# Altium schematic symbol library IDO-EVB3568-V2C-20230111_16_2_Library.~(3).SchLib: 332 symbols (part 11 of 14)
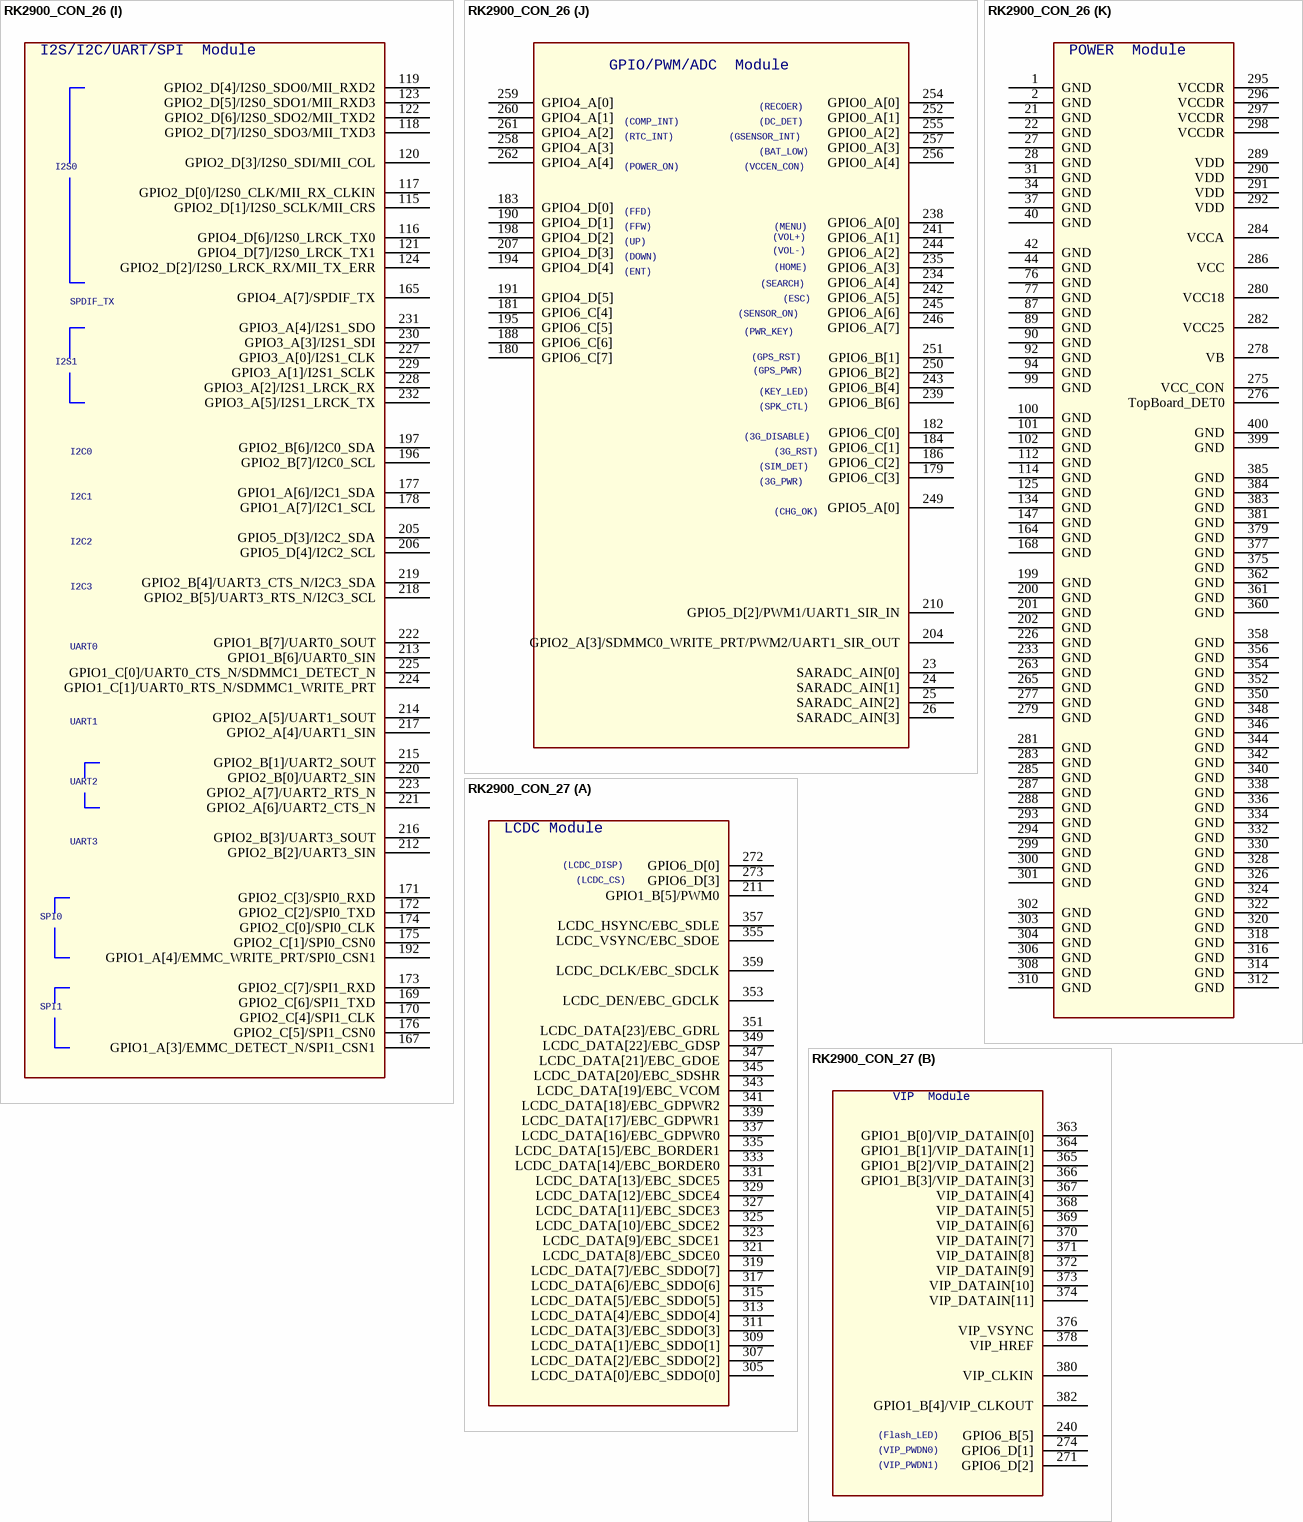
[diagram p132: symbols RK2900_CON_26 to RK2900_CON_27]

## RK2900_CON_26
designator U?
Altium-Right: 120; Altium-Bottom: 650; Altium-Right1: 160; Altium-Bottom1: 390; Altium-Right2: 140; Altium-Bottom2: 270; Altium-Right3: 280; Altium-Bottom3: 520; Altium-Right4: 170; Altium-Bottom4: 240; Altium-Right5: 190; Altium-Bottom5: 530; Altium-Right6: 290; Altium-Bottom6: 300; Altium-Right7: 220; Altium-Bottom7: 340; Altium-Right8: 180; Altium-Bottom8: 200; Altium-Bottom9: 690; Altium-Right10: 250; Altium-Bottom10: 470
footprint RK2900_TOP
part A pins: 211 GPIO1_B[5]/PWM0, 272 GPIO6_D[0], 273 GPIO6_D[3], 305 LCDC_DATA[0]/EBC_SDDO[0], 307 LCDC_DATA[2]/EBC_SDDO[2], 309 LCDC_DATA[1]/EBC_SDDO[1], 311 LCDC_DATA[3]/EBC_SDDO[3], 313 LCDC_DATA[4]/EBC_SDDO[4], 315 LCDC_DATA[5]/EBC_SDDO[5], 317 LCDC_DATA[6]/EBC_SDDO[6], 319 LCDC_DATA[7]/EBC_SDDO[7], 321 LCDC_DATA[8]/EBC_SDCE0, 323 LCDC_DATA[9]/EBC_SDCE1, 325 LCDC_DATA[10]/EBC_SDCE2, 327 LCDC_DATA[11]/EBC_SDCE3, 329 LCDC_DATA[12]/EBC_SDCE4, 331 LCDC_DATA[13]/EBC_SDCE5, 333 LCDC_DATA[14]/EBC_BORDER0, 335 LCDC_DATA[15]/EBC_BORDER1, 337 LCDC_DATA[16]/EBC_GDPWR0, 339 LCDC_DATA[17]/EBC_GDPWR1, 341 LCDC_DATA[18]/EBC_GDPWR2, 343 LCDC_DATA[19]/EBC_VCOM, 345 LCDC_DATA[20]/EBC_SDSHR, 347 LCDC_DATA[21]/EBC_GDOE, 349 LCDC_DATA[22]/EBC_GDSP, 351 LCDC_DATA[23]/EBC_GDRL, 353 LCDC_DEN/EBC_GDCLK, 355 LCDC_VSYNC/EBC_SDOE, 357 LCDC_HSYNC/EBC_SDLE, 359 LCDC_DCLK/EBC_SDCLK
part B pins: 240 GPIO6_B[5], 271 GPIO6_D[2], 274 GPIO6_D[1], 363 GPIO1_B[0]/VIP_DATAIN[0], 364 GPIO1_B[1]/VIP_DATAIN[1], 365 GPIO1_B[2]/VIP_DATAIN[2], 366 GPIO1_B[3]/VIP_DATAIN[3], 367 VIP_DATAIN[4], 368 VIP_DATAIN[5], 369 VIP_DATAIN[6], 370 VIP_DATAIN[7], 371 VIP_DATAIN[8], 372 VIP_DATAIN[9], 373 VIP_DATAIN[10], 374 VIP_DATAIN[11], 376 VIP_VSYNC, 378 VIP_HREF, 380 VIP_CLKIN, 382 GPIO1_B[4]/VIP_CLKOUT
part C pins: 3 GPIO0_C[6]/EBC_SDCE4/SMC_DATA[14], 4 GPIO0_C[7]/EBC_SDCE5/SMC_DATA[15], 5 GPIO0_C[0]/EBC_GDSP/SMC_DATA[8], 6 GPIO0_C[1]/EBC_GDRL/SMC_DATA[9], 7 GPIO0_B[3]/EBC_BORDER0/SMC_ADDR[3]/HOST_DATA[3], 8 GPIO0_B[4]/EBC_BORDER1/SMC_WEN, 9 GPIO0_D[1]/EBC_GDCLK/SMC_ADDR[4]/HOST_DATA[4], 10 GPIO0_B[2]/EBC_SDCE2/SMC_ADDR[2]/HOST_DATA[2], 11 GPIO0_C[3]/EBC_GDPWR1/SMC_DATA[11], 12 GPIO0_B[7]/EBC_GDOE/SMC_OEN, 13 GPIO0_D[0]/EBC_SDOE/SMC_ADVN, 14 GPIO5_C[6]/EBC_SDDO[6]/SMC_DATA[6], 15 GPIO0_C[5]/EBC_SDCE3/SMC_DATA[13], 16 GPIO0_B[1]/EBC_SDCE1/SMC_ADDR[1]/HOST_DATA[1], 17 GPIO5_C[5]/EBC_SDDO[5]/SMC_DATA[5], 18 GPIO3_D[5]/SMC_ADDR[7]/HOST_DATA[7], 19 GPIO1_A[2]/SMC_CSN1, 20 GPIO0_C[4]/EBC_GDPWR2/SMC_DATA[12], 43 GPIO3_D[6]/SMC_ADDR[8]/HOST_DATA[8], 150 GPIO3_D[4]/HOST_WRN, 151 GPIO3_D[3]/HOST_RDN, 152 GPIO3_D[2]/HOST_CSN, 153 GPIO3_D[7]/SMC_ADDR[9]/HOST_DATA[9], 154 GPIO3_A[6]/SMC_ADDR[14]/HOST_DATA[14], 155 GPIO3_C[7]/SMC_ADDR[17]/HOST_DATA[17], 156 GPIO3_C[3]/SMC_ADDR[10]/HOST_DATA[10], 157 GPIO3_C[4]/SMC_ADDR[11]/HOST_DATA[11], 158 GPIO3_D[1]/SMC_ADDR[19]/HOST_ADDR1, 159 GPIO3_C[5]/SMC_ADDR[12]/HOST_DATA[12], 160 GPIO3_C[2]/SMC_ADDR[13]/HOST_DATA[13], 161 GPIO3_C[6]/SMC_ADDR[16]/HOST_DATA[16], 162 GPIO3_A[7]/SMC_ADDR[15]/HOST_DATA[15], 163 GPIO3_D[0]/SMC_ADDR[18]/HOST_ADDR0, 386 GPIO1_A[1]/SMC_CSN0, 387 GPIO5_C[4]/EBC_SDDO[4]/SMC_DATA[4], 388 GPIO5_D[1]/EBC_SDCLK/SMC_ADDR[6]/HOST_DATA[6], 389 GPIO0_B[5]/EBC_VCOM/SMC_BLSN0, 390 GPIO5_C[0]/EBC_SDDO[0]/SMC_DATA[0], 391 GPIO5_D[0]/EBC_SDLE/SMC_ADDR[5]/HOST_DATA[5], 392 GPIO5_C[1]/EBC_SDDO[1]/SMC_DATA[1], 393 GPIO0_B[6]/EBC_SDSHR/SMC_BLSN1/HOST_INT, 394 GPIO0_C[2]/EBC_GDPWR0/SMC_DATA[10], 395 GPIO5_C[2]/EBC_SDDO[2]/SMC_DATA[2], 396 GPIO5_C[3]/EBC_SDDO[3]/SMC_DATA[3], 397 GPIO5_C[7]/EBC_SDDO[7]/SMC_DATA[7], 398 GPIO0_B[0]/EBC_SDCE0/SMC_ADDR[0]/HOST_DATA[0]
part D pins: 29 OTG_DP, 30 OTG_DM, 32 HOST20_DM, 33 HOST20_DP, 35 HOST11_DM, 36 HOST11_DP, 38 OTG_ID, 39 OTG_VBUS, 41 RTCINT_OUT, 166 GPIO4_A[5]/OTG_DRV_VBUS, 187 GPIO4_A[6]/HOST20_DRV_VBUS, 264 NPOR
part E pins: 45 FLASH_ALE, 46 FLASH_DATA[1], 47 FLASH_RDY, 48 FLASH_RDN, 49 GPIO4_B[4]/FLASH_DATA[12], 50 FLASH_DATA[0], 51 FLASH_DATA[4], 52 GPIO4_B[7]/FLASH_DATA[15], 53 GPIO4_B[5]/FLASH_DATA[13], 54 FLASH_CLE, 55 GPIO4_B[1]/FLASH_DATA[9], 56 FLASH_DATA[5], 57 FLASH_CSN0, 58 FLASH_DATA[6], 59 GPIO4_B[0]/FLASH_DATA[8], 60 FLASH_DATA[7], 61 FLASH_DATA[2], 62 FLASH_DATA[3], 63 GPIO0_D[7]/FLASH_CSN6, 64 FLASH_WP, 65 FLASH_WRN, 66 GPIO4_B[6]/FLASH_DATA[14], 67 GPIO0_D[3]/FLASH_CSN2, 68 GPIO0_D[4]/FLASH_CSN3, 69 GPIO0_D[2]/FLASH_CSN1, 70 GPIO0_D[6]/FLASH_CSN5, 71 GPIO1_A[0]/FLASH_CSN7/MDDR_TQ, 72 GPIO0_A[5]/FLASH_DQS, 73 GPIO0_D[5]/FLASH_CSN4, 74 GPIO4_B[2]/FLASH_DATA[10], 75 GPIO4_B[3]/FLASH_DATA[11], 78 GPIO3_B[3]/EMMC_DATA1, 79 GPIO3_B[1]/EMMC_CMD, 80 GPIO3_B[6]/EMMC_DATA4, 81 GPIO3_C[1]/EMMC_DATA7, 82 GPIO3_B[5]/EMMC_DATA3, 83 GPIO3_B[4]/EMMC_DATA2, 84 GPIO3_B[2]/EMMC_DATA0, 85 GPIO3_C[0]/EMMC_DATA6, 86 GPIO3_B[7]/EMMC_DATA5, 88 GPIO3_B[0]/EMMC_CLKOUT, 203 GPIO1_A[5]/EMMC_PWR_EN/PWM3, 237 GPIO6_B[7]
part F pins: 91 GPIO1_C[2]/SDMMC1_CMD, 93 GPIO1_C[7]/SDMMC1_CLKOUT, 95 GPIO1_C[4]/SDMMC1_DATA1, 96 GPIO1_C[3]/SDMMC1_DATA0, 97 GPIO1_C[6]/SDMMC1_DATA3, 98 GPIO1_C[5]/SDMMC1_DATA2, 103 GPIO1_D[3]/SDMMC0_DATA1, 104 GPIO1_D[1]/SDMMC0_CMD, 105 GPIO1_D[5]/SDMMC0_DATA3, 106 GPIO2_A[1]/SDMMC0_DATA7, 107 GPIO1_D[7]/SDMMC0_DATA5, 108 GPIO1_D[2]/SDMMC0_DATA0, 109 GPIO2_A[0]/SDMMC0_DATA6, 110 GPIO1_D[6]/SDMMC0_DATA4, 111 GPIO1_D[4]/SDMMC0_DATA2, 113 GPIO1_D[0]/SDMMC0_CLKOUT, 185 GPIO5_D[7], 193 GPIO2_A[2]/SDMMC0_DETECT_N, 208 GPIO5_D[5]/SDMMC0_PWR_EN, 209 GPIO5_D[6]/SDMMC1_PWR_EN
part G pins: 126 GPIO4_C[7]/RMII_RXD0/MII_RXD0, 127 GPIO4_C[3]/RMII_TXD0/MII_TXD0, 128 GPIO4_C[6]/RMII_RXD1/MII_RXD1, 129 GPIO4_C[1]/RMII_TX_EN/MII_TX_EN, 130 GPIO4_C[0]/RMII_CLKOUT/RMII_CLKIN, 131 GPIO4_C[2]/RMII_TXD1/MII_TXD1, 132 GPIO4_C[5]/RMII_CRS_DVALID/MII_RXD_VALID, 133 GPIO4_C[4]/RMII_RX_ERR/MII_RX_ERR, 148 GPIO5_A[3]/MII_TX_CLKIN, 149 GPIO0_A[6]/MII_MD, 189 GPIO0_A[7]/MII_MDCLK, 236 GPIO5_A[2], 248 GPIO6_B[0], 253 GPIO5_A[1], 266 TRST_N, 267 TCK, 268 TDI, 269 TMS, 270 TDO
part H pins: 135 GPIO5_A[7]/HSADC_DATA2, 136 GPIO5_B[5]/HSADC_DATA8/TS_VALID, 137 GPIO5_A[5]/HSADC_DATA0, 138 GPIO5_B[1]/HSADC_DATA4, 139 GPIO5_B[0]/HSADC_DATA3, 140 GPIO5_A[6]/HSADC_DATA1, 141 GPIO5_B[3]/HSADC_DATA6, 142 GPIO5_B[2]/HSADC_DATA5, 143 GPIO5_B[4]/HSADC_DATA7, 144 GPIO5_A[4]/TS_SYNC, 145 GPIO5_B[6]/HSADC_DATA9/TS_FAIL, 146 GPIO5_B[7]/HSADC_CLKOUT/GPS_CLK, 247 GPIO6_B[3]
part I pins: 115 GPIO2_D[1]/I2S0_SCLK/MII_CRS, 116 GPIO4_D[6]/I2S0_LRCK_TX0, 117 GPIO2_D[0]/I2S0_CLK/MII_RX_CLKIN, 118 GPIO2_D[7]/I2S0_SDO3/MII_TXD3, 119 GPIO2_D[4]/I2S0_SDO0/MII_RXD2, 120 GPIO2_D[3]/I2S0_SDI/MII_COL, 121 GPIO4_D[7]/I2S0_LRCK_TX1, 122 GPIO2_D[6]/I2S0_SDO2/MII_TXD2, 123 GPIO2_D[5]/I2S0_SDO1/MII_RXD3, 124 GPIO2_D[2]/I2S0_LRCK_RX/MII_TX_ERR, 165 GPIO4_A[7]/SPDIF_TX, 167 GPIO1_A[3]/EMMC_DETECT_N/SPI1_CSN1, 169 GPIO2_C[6]/SPI1_TXD, 170 GPIO2_C[4]/SPI1_CLK, 171 GPIO2_C[3]/SPI0_RXD, 172 GPIO2_C[2]/SPI0_TXD, 173 GPIO2_C[7]/SPI1_RXD, 174 GPIO2_C[0]/SPI0_CLK, 175 GPIO2_C[1]/SPI0_CSN0, 176 GPIO2_C[5]/SPI1_CSN0, 177 GPIO1_A[6]/I2C1_SDA, 178 GPIO1_A[7]/I2C1_SCL, 192 GPIO1_A[4]/EMMC_WRITE_PRT/SPI0_CSN1, 196 GPIO2_B[7]/I2C0_SCL, 197 GPIO2_B[6]/I2C0_SDA, 205 GPIO5_D[3]/I2C2_SDA, 206 GPIO5_D[4]/I2C2_SCL, 212 GPIO2_B[2]/UART3_SIN, 213 GPIO1_B[6]/UART0_SIN, 214 GPIO2_A[5]/UART1_SOUT, 215 GPIO2_B[1]/UART2_SOUT, 216 GPIO2_B[3]/UART3_SOUT, 217 GPIO2_A[4]/UART1_SIN, 218 GPIO2_B[5]/UART3_RTS_N/I2C3_SCL, 219 GPIO2_B[4]/UART3_CTS_N/I2C3_SDA, 220 GPIO2_B[0]/UART2_SIN, 221 GPIO2_A[6]/UART2_CTS_N, 222 GPIO1_B[7]/UART0_SOUT, 223 GPIO2_A[7]/UART2_RTS_N, 224 GPIO1_C[1]/UART0_RTS_N/SDMMC1_WRITE_PRT, 225 GPIO1_C[0]/UART0_CTS_N/SDMMC1_DETECT_N, 227 GPIO3_A[0]/I2S1_CLK, 228 GPIO3_A[2]/I2S1_LRCK_RX, 229 GPIO3_A[1]/I2S1_SCLK, 230 GPIO3_A[3]/I2S1_SDI, 231 GPIO3_A[4]/I2S1_SDO, 232 GPIO3_A[5]/I2S1_LRCK_TX
part J pins: 23 SARADC_AIN[0], 24 SARADC_AIN[1], 25 SARADC_AIN[2], 26 SARADC_AIN[3], 179 GPIO6_C[3], 180 GPIO6_C[7], 181 GPIO6_C[4], 182 GPIO6_C[0], 183 GPIO4_D[0], 184 GPIO6_C[1], 186 GPIO6_C[2], 188 GPIO6_C[6], 190 GPIO4_D[1], 191 GPIO4_D[5], 194 GPIO4_D[4], 195 GPIO6_C[5], 198 GPIO4_D[2], 204 GPIO2_A[3]/SDMMC0_WRITE_PRT/PWM2/UART1_SIR_OUT, 207 GPIO4_D[3], 210 GPIO5_D[2]/PWM1/UART1_SIR_IN, 234 GPIO6_A[4], 235 GPIO6_A[3], 238 GPIO6_A[0], 239 GPIO6_B[6], 241 GPIO6_A[1], 242 GPIO6_A[5], 243 GPIO6_B[4], 244 GPIO6_A[2], 245 GPIO6_A[6], 246 GPIO6_A[7], 249 GPIO5_A[0], 250 GPIO6_B[2], 251 GPIO6_B[1], 252 GPIO0_A[1], 254 GPIO0_A[0], 255 GPIO0_A[2], 256 GPIO0_A[4], 257 GPIO0_A[3], 258 GPIO4_A[3], 259 GPIO4_A[0], 260 GPIO4_A[1], 261 GPIO4_A[2], 262 GPIO4_A[4]
part K pins: 1 GND, 2 GND, 21 GND, 22 GND, 27 GND, 28 GND, 31 GND, 34 GND, 37 GND, 40 GND, 42 GND, 44 GND, 76 GND, 77 GND, 87 GND, 89 GND, 90 GND, 92 GND, 94 GND, 99 GND, 100 GND, 101 GND, 102 GND, 112 GND, 114 GND, 125 GND, 134 GND, 147 GND, 164 GND, 168 GND, 199 GND, 200 GND, 201 GND, 202 GND, 226 GND, 233 GND, 263 GND, 265 GND, 275 VCC_CON, 276 TopBoard_DET0, 277 GND, 278 VB, 279 GND, 280 VCC18, 281 GND, 282 VCC25, 283 GND, 284 VCCA, 285 GND, 286 VCC, 287 GND, 288 GND, 289 VDD, 290 VDD, 291 VDD, 292 VDD, 293 GND, 294 GND, 295 VCCDR, 296 VCCDR, 297 VCCDR, 298 VCCDR, 299 GND, 300 GND, 301 GND, 302 GND, 303 GND, 304 GND, 306 GND, 308 GND, 310 GND, 312 GND, 314 GND, 316 GND, 318 GND, 320 GND, 322 GND, 324 GND, 326 GND, 328 GND, 330 GND, 332 GND, 334 GND, 336 GND, 338 GND, 340 GND, 342 GND, 344 GND, 346 GND, 348 GND, 350 GND, 352 GND, 354 GND, 356 GND, 358 GND, 360 GND, 361 GND, 362 GND, 375 GND, 377 GND, 379 GND, 381 GND, 383 GND, 384 GND, 385 GND, 399 GND, 400 GND

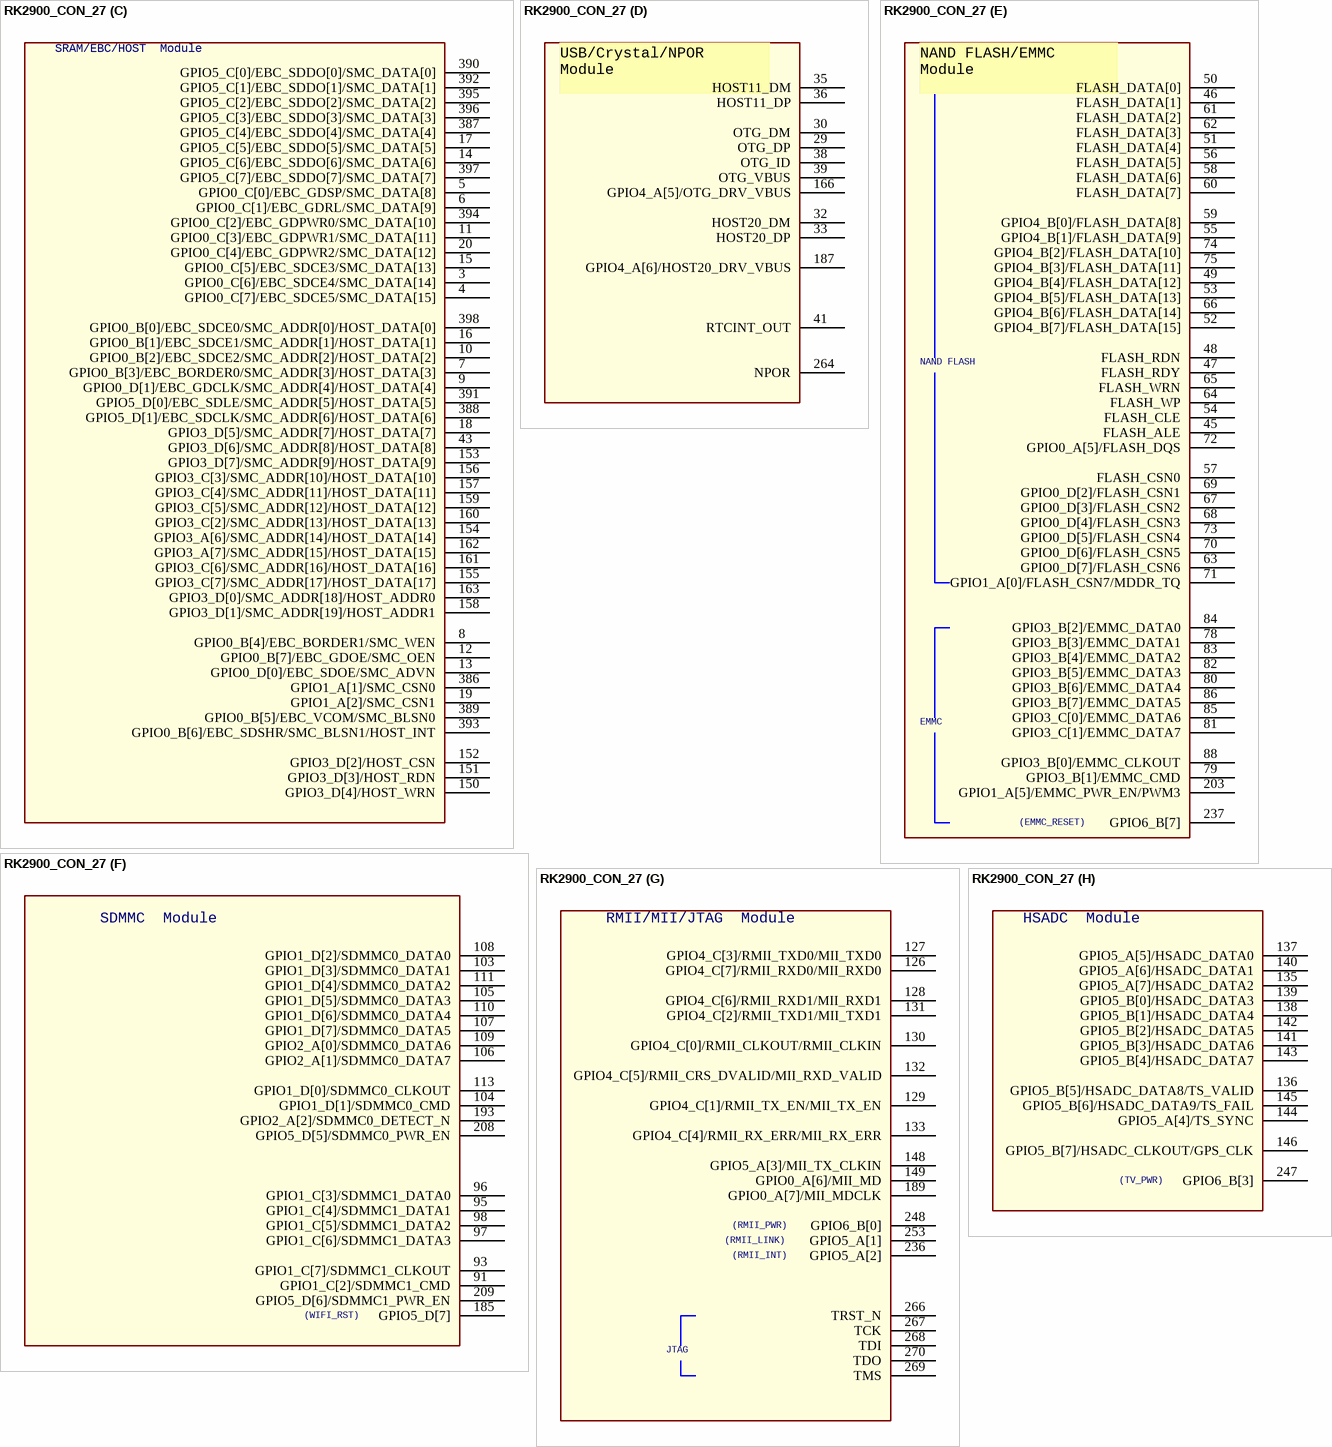
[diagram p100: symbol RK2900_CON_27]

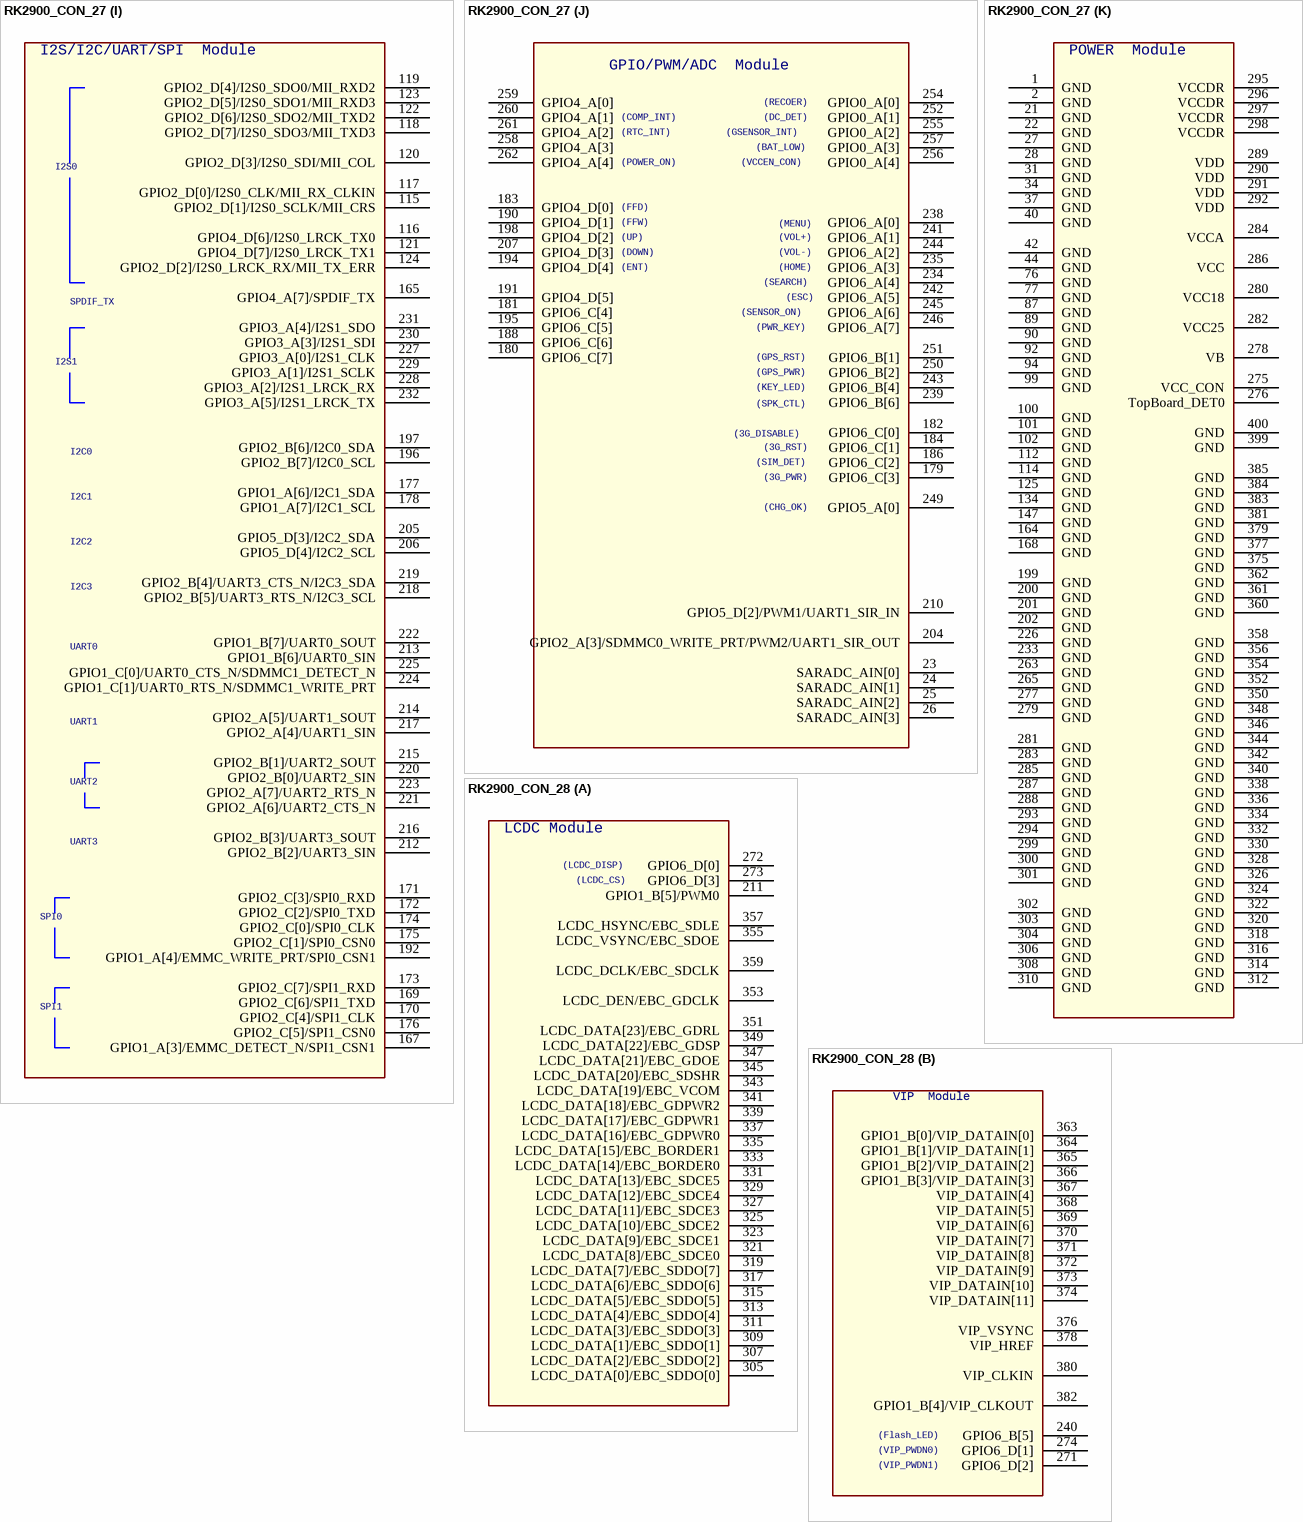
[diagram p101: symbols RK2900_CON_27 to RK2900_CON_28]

## RK2900_CON_27
designator U?
Altium-Right: 160; Altium-Bottom: 390; Altium-Right1: 140; Altium-Bottom1: 270; Altium-Right2: 280; Altium-Bottom2: 520; Altium-Right3: 170; Altium-Bottom3: 240; Altium-Right4: 190; Altium-Bottom4: 530; Altium-Right5: 290; Altium-Bottom5: 300; Altium-Right6: 220; Altium-Bottom6: 340; Altium-Right7: 180; Altium-Bottom7: 200; Altium-Bottom8: 690; Altium-Right9: 250; Altium-Bottom9: 470; Altium-Right10: 120; Altium-Bottom10: 650
footprint RK2900_TOP
part A pins: 211 GPIO1_B[5]/PWM0, 272 GPIO6_D[0], 273 GPIO6_D[3], 305 LCDC_DATA[0]/EBC_SDDO[0], 307 LCDC_DATA[2]/EBC_SDDO[2], 309 LCDC_DATA[1]/EBC_SDDO[1], 311 LCDC_DATA[3]/EBC_SDDO[3], 313 LCDC_DATA[4]/EBC_SDDO[4], 315 LCDC_DATA[5]/EBC_SDDO[5], 317 LCDC_DATA[6]/EBC_SDDO[6], 319 LCDC_DATA[7]/EBC_SDDO[7], 321 LCDC_DATA[8]/EBC_SDCE0, 323 LCDC_DATA[9]/EBC_SDCE1, 325 LCDC_DATA[10]/EBC_SDCE2, 327 LCDC_DATA[11]/EBC_SDCE3, 329 LCDC_DATA[12]/EBC_SDCE4, 331 LCDC_DATA[13]/EBC_SDCE5, 333 LCDC_DATA[14]/EBC_BORDER0, 335 LCDC_DATA[15]/EBC_BORDER1, 337 LCDC_DATA[16]/EBC_GDPWR0, 339 LCDC_DATA[17]/EBC_GDPWR1, 341 LCDC_DATA[18]/EBC_GDPWR2, 343 LCDC_DATA[19]/EBC_VCOM, 345 LCDC_DATA[20]/EBC_SDSHR, 347 LCDC_DATA[21]/EBC_GDOE, 349 LCDC_DATA[22]/EBC_GDSP, 351 LCDC_DATA[23]/EBC_GDRL, 353 LCDC_DEN/EBC_GDCLK, 355 LCDC_VSYNC/EBC_SDOE, 357 LCDC_HSYNC/EBC_SDLE, 359 LCDC_DCLK/EBC_SDCLK
part B pins: 240 GPIO6_B[5], 271 GPIO6_D[2], 274 GPIO6_D[1], 363 GPIO1_B[0]/VIP_DATAIN[0], 364 GPIO1_B[1]/VIP_DATAIN[1], 365 GPIO1_B[2]/VIP_DATAIN[2], 366 GPIO1_B[3]/VIP_DATAIN[3], 367 VIP_DATAIN[4], 368 VIP_DATAIN[5], 369 VIP_DATAIN[6], 370 VIP_DATAIN[7], 371 VIP_DATAIN[8], 372 VIP_DATAIN[9], 373 VIP_DATAIN[10], 374 VIP_DATAIN[11], 376 VIP_VSYNC, 378 VIP_HREF, 380 VIP_CLKIN, 382 GPIO1_B[4]/VIP_CLKOUT
part C pins: 3 GPIO0_C[6]/EBC_SDCE4/SMC_DATA[14], 4 GPIO0_C[7]/EBC_SDCE5/SMC_DATA[15], 5 GPIO0_C[0]/EBC_GDSP/SMC_DATA[8], 6 GPIO0_C[1]/EBC_GDRL/SMC_DATA[9], 7 GPIO0_B[3]/EBC_BORDER0/SMC_ADDR[3]/HOST_DATA[3], 8 GPIO0_B[4]/EBC_BORDER1/SMC_WEN, 9 GPIO0_D[1]/EBC_GDCLK/SMC_ADDR[4]/HOST_DATA[4], 10 GPIO0_B[2]/EBC_SDCE2/SMC_ADDR[2]/HOST_DATA[2], 11 GPIO0_C[3]/EBC_GDPWR1/SMC_DATA[11], 12 GPIO0_B[7]/EBC_GDOE/SMC_OEN, 13 GPIO0_D[0]/EBC_SDOE/SMC_ADVN, 14 GPIO5_C[6]/EBC_SDDO[6]/SMC_DATA[6], 15 GPIO0_C[5]/EBC_SDCE3/SMC_DATA[13], 16 GPIO0_B[1]/EBC_SDCE1/SMC_ADDR[1]/HOST_DATA[1], 17 GPIO5_C[5]/EBC_SDDO[5]/SMC_DATA[5], 18 GPIO3_D[5]/SMC_ADDR[7]/HOST_DATA[7], 19 GPIO1_A[2]/SMC_CSN1, 20 GPIO0_C[4]/EBC_GDPWR2/SMC_DATA[12], 43 GPIO3_D[6]/SMC_ADDR[8]/HOST_DATA[8], 150 GPIO3_D[4]/HOST_WRN, 151 GPIO3_D[3]/HOST_RDN, 152 GPIO3_D[2]/HOST_CSN, 153 GPIO3_D[7]/SMC_ADDR[9]/HOST_DATA[9], 154 GPIO3_A[6]/SMC_ADDR[14]/HOST_DATA[14], 155 GPIO3_C[7]/SMC_ADDR[17]/HOST_DATA[17], 156 GPIO3_C[3]/SMC_ADDR[10]/HOST_DATA[10], 157 GPIO3_C[4]/SMC_ADDR[11]/HOST_DATA[11], 158 GPIO3_D[1]/SMC_ADDR[19]/HOST_ADDR1, 159 GPIO3_C[5]/SMC_ADDR[12]/HOST_DATA[12], 160 GPIO3_C[2]/SMC_ADDR[13]/HOST_DATA[13], 161 GPIO3_C[6]/SMC_ADDR[16]/HOST_DATA[16], 162 GPIO3_A[7]/SMC_ADDR[15]/HOST_DATA[15], 163 GPIO3_D[0]/SMC_ADDR[18]/HOST_ADDR0, 386 GPIO1_A[1]/SMC_CSN0, 387 GPIO5_C[4]/EBC_SDDO[4]/SMC_DATA[4], 388 GPIO5_D[1]/EBC_SDCLK/SMC_ADDR[6]/HOST_DATA[6], 389 GPIO0_B[5]/EBC_VCOM/SMC_BLSN0, 390 GPIO5_C[0]/EBC_SDDO[0]/SMC_DATA[0], 391 GPIO5_D[0]/EBC_SDLE/SMC_ADDR[5]/HOST_DATA[5], 392 GPIO5_C[1]/EBC_SDDO[1]/SMC_DATA[1], 393 GPIO0_B[6]/EBC_SDSHR/SMC_BLSN1/HOST_INT, 394 GPIO0_C[2]/EBC_GDPWR0/SMC_DATA[10], 395 GPIO5_C[2]/EBC_SDDO[2]/SMC_DATA[2], 396 GPIO5_C[3]/EBC_SDDO[3]/SMC_DATA[3], 397 GPIO5_C[7]/EBC_SDDO[7]/SMC_DATA[7], 398 GPIO0_B[0]/EBC_SDCE0/SMC_ADDR[0]/HOST_DATA[0]
part D pins: 29 OTG_DP, 30 OTG_DM, 32 HOST20_DM, 33 HOST20_DP, 35 HOST11_DM, 36 HOST11_DP, 38 OTG_ID, 39 OTG_VBUS, 41 RTCINT_OUT, 166 GPIO4_A[5]/OTG_DRV_VBUS, 187 GPIO4_A[6]/HOST20_DRV_VBUS, 264 NPOR
part E pins: 45 FLASH_ALE, 46 FLASH_DATA[1], 47 FLASH_RDY, 48 FLASH_RDN, 49 GPIO4_B[4]/FLASH_DATA[12], 50 FLASH_DATA[0], 51 FLASH_DATA[4], 52 GPIO4_B[7]/FLASH_DATA[15], 53 GPIO4_B[5]/FLASH_DATA[13], 54 FLASH_CLE, 55 GPIO4_B[1]/FLASH_DATA[9], 56 FLASH_DATA[5], 57 FLASH_CSN0, 58 FLASH_DATA[6], 59 GPIO4_B[0]/FLASH_DATA[8], 60 FLASH_DATA[7], 61 FLASH_DATA[2], 62 FLASH_DATA[3], 63 GPIO0_D[7]/FLASH_CSN6, 64 FLASH_WP, 65 FLASH_WRN, 66 GPIO4_B[6]/FLASH_DATA[14], 67 GPIO0_D[3]/FLASH_CSN2, 68 GPIO0_D[4]/FLASH_CSN3, 69 GPIO0_D[2]/FLASH_CSN1, 70 GPIO0_D[6]/FLASH_CSN5, 71 GPIO1_A[0]/FLASH_CSN7/MDDR_TQ, 72 GPIO0_A[5]/FLASH_DQS, 73 GPIO0_D[5]/FLASH_CSN4, 74 GPIO4_B[2]/FLASH_DATA[10], 75 GPIO4_B[3]/FLASH_DATA[11], 78 GPIO3_B[3]/EMMC_DATA1, 79 GPIO3_B[1]/EMMC_CMD, 80 GPIO3_B[6]/EMMC_DATA4, 81 GPIO3_C[1]/EMMC_DATA7, 82 GPIO3_B[5]/EMMC_DATA3, 83 GPIO3_B[4]/EMMC_DATA2, 84 GPIO3_B[2]/EMMC_DATA0, 85 GPIO3_C[0]/EMMC_DATA6, 86 GPIO3_B[7]/EMMC_DATA5, 88 GPIO3_B[0]/EMMC_CLKOUT, 203 GPIO1_A[5]/EMMC_PWR_EN/PWM3, 237 GPIO6_B[7]
part F pins: 91 GPIO1_C[2]/SDMMC1_CMD, 93 GPIO1_C[7]/SDMMC1_CLKOUT, 95 GPIO1_C[4]/SDMMC1_DATA1, 96 GPIO1_C[3]/SDMMC1_DATA0, 97 GPIO1_C[6]/SDMMC1_DATA3, 98 GPIO1_C[5]/SDMMC1_DATA2, 103 GPIO1_D[3]/SDMMC0_DATA1, 104 GPIO1_D[1]/SDMMC0_CMD, 105 GPIO1_D[5]/SDMMC0_DATA3, 106 GPIO2_A[1]/SDMMC0_DATA7, 107 GPIO1_D[7]/SDMMC0_DATA5, 108 GPIO1_D[2]/SDMMC0_DATA0, 109 GPIO2_A[0]/SDMMC0_DATA6, 110 GPIO1_D[6]/SDMMC0_DATA4, 111 GPIO1_D[4]/SDMMC0_DATA2, 113 GPIO1_D[0]/SDMMC0_CLKOUT, 185 GPIO5_D[7], 193 GPIO2_A[2]/SDMMC0_DETECT_N, 208 GPIO5_D[5]/SDMMC0_PWR_EN, 209 GPIO5_D[6]/SDMMC1_PWR_EN
part G pins: 126 GPIO4_C[7]/RMII_RXD0/MII_RXD0, 127 GPIO4_C[3]/RMII_TXD0/MII_TXD0, 128 GPIO4_C[6]/RMII_RXD1/MII_RXD1, 129 GPIO4_C[1]/RMII_TX_EN/MII_TX_EN, 130 GPIO4_C[0]/RMII_CLKOUT/RMII_CLKIN, 131 GPIO4_C[2]/RMII_TXD1/MII_TXD1, 132 GPIO4_C[5]/RMII_CRS_DVALID/MII_RXD_VALID, 133 GPIO4_C[4]/RMII_RX_ERR/MII_RX_ERR, 148 GPIO5_A[3]/MII_TX_CLKIN, 149 GPIO0_A[6]/MII_MD, 189 GPIO0_A[7]/MII_MDCLK, 236 GPIO5_A[2], 248 GPIO6_B[0], 253 GPIO5_A[1], 266 TRST_N, 267 TCK, 268 TDI, 269 TMS, 270 TDO
part H pins: 135 GPIO5_A[7]/HSADC_DATA2, 136 GPIO5_B[5]/HSADC_DATA8/TS_VALID, 137 GPIO5_A[5]/HSADC_DATA0, 138 GPIO5_B[1]/HSADC_DATA4, 139 GPIO5_B[0]/HSADC_DATA3, 140 GPIO5_A[6]/HSADC_DATA1, 141 GPIO5_B[3]/HSADC_DATA6, 142 GPIO5_B[2]/HSADC_DATA5, 143 GPIO5_B[4]/HSADC_DATA7, 144 GPIO5_A[4]/TS_SYNC, 145 GPIO5_B[6]/HSADC_DATA9/TS_FAIL, 146 GPIO5_B[7]/HSADC_CLKOUT/GPS_CLK, 247 GPIO6_B[3]
part I pins: 115 GPIO2_D[1]/I2S0_SCLK/MII_CRS, 116 GPIO4_D[6]/I2S0_LRCK_TX0, 117 GPIO2_D[0]/I2S0_CLK/MII_RX_CLKIN, 118 GPIO2_D[7]/I2S0_SDO3/MII_TXD3, 119 GPIO2_D[4]/I2S0_SDO0/MII_RXD2, 120 GPIO2_D[3]/I2S0_SDI/MII_COL, 121 GPIO4_D[7]/I2S0_LRCK_TX1, 122 GPIO2_D[6]/I2S0_SDO2/MII_TXD2, 123 GPIO2_D[5]/I2S0_SDO1/MII_RXD3, 124 GPIO2_D[2]/I2S0_LRCK_RX/MII_TX_ERR, 165 GPIO4_A[7]/SPDIF_TX, 167 GPIO1_A[3]/EMMC_DETECT_N/SPI1_CSN1, 169 GPIO2_C[6]/SPI1_TXD, 170 GPIO2_C[4]/SPI1_CLK, 171 GPIO2_C[3]/SPI0_RXD, 172 GPIO2_C[2]/SPI0_TXD, 173 GPIO2_C[7]/SPI1_RXD, 174 GPIO2_C[0]/SPI0_CLK, 175 GPIO2_C[1]/SPI0_CSN0, 176 GPIO2_C[5]/SPI1_CSN0, 177 GPIO1_A[6]/I2C1_SDA, 178 GPIO1_A[7]/I2C1_SCL, 192 GPIO1_A[4]/EMMC_WRITE_PRT/SPI0_CSN1, 196 GPIO2_B[7]/I2C0_SCL, 197 GPIO2_B[6]/I2C0_SDA, 205 GPIO5_D[3]/I2C2_SDA, 206 GPIO5_D[4]/I2C2_SCL, 212 GPIO2_B[2]/UART3_SIN, 213 GPIO1_B[6]/UART0_SIN, 214 GPIO2_A[5]/UART1_SOUT, 215 GPIO2_B[1]/UART2_SOUT, 216 GPIO2_B[3]/UART3_SOUT, 217 GPIO2_A[4]/UART1_SIN, 218 GPIO2_B[5]/UART3_RTS_N/I2C3_SCL, 219 GPIO2_B[4]/UART3_CTS_N/I2C3_SDA, 220 GPIO2_B[0]/UART2_SIN, 221 GPIO2_A[6]/UART2_CTS_N, 222 GPIO1_B[7]/UART0_SOUT, 223 GPIO2_A[7]/UART2_RTS_N, 224 GPIO1_C[1]/UART0_RTS_N/SDMMC1_WRITE_PRT, 225 GPIO1_C[0]/UART0_CTS_N/SDMMC1_DETECT_N, 227 GPIO3_A[0]/I2S1_CLK, 228 GPIO3_A[2]/I2S1_LRCK_RX, 229 GPIO3_A[1]/I2S1_SCLK, 230 GPIO3_A[3]/I2S1_SDI, 231 GPIO3_A[4]/I2S1_SDO, 232 GPIO3_A[5]/I2S1_LRCK_TX
part J pins: 23 SARADC_AIN[0], 24 SARADC_AIN[1], 25 SARADC_AIN[2], 26 SARADC_AIN[3], 179 GPIO6_C[3], 180 GPIO6_C[7], 181 GPIO6_C[4], 182 GPIO6_C[0], 183 GPIO4_D[0], 184 GPIO6_C[1], 186 GPIO6_C[2], 188 GPIO6_C[6], 190 GPIO4_D[1], 191 GPIO4_D[5], 194 GPIO4_D[4], 195 GPIO6_C[5], 198 GPIO4_D[2], 204 GPIO2_A[3]/SDMMC0_WRITE_PRT/PWM2/UART1_SIR_OUT, 207 GPIO4_D[3], 210 GPIO5_D[2]/PWM1/UART1_SIR_IN, 234 GPIO6_A[4], 235 GPIO6_A[3], 238 GPIO6_A[0], 239 GPIO6_B[6], 241 GPIO6_A[1], 242 GPIO6_A[5], 243 GPIO6_B[4], 244 GPIO6_A[2], 245 GPIO6_A[6], 246 GPIO6_A[7], 249 GPIO5_A[0], 250 GPIO6_B[2], 251 GPIO6_B[1], 252 GPIO0_A[1], 254 GPIO0_A[0], 255 GPIO0_A[2], 256 GPIO0_A[4], 257 GPIO0_A[3], 258 GPIO4_A[3], 259 GPIO4_A[0], 260 GPIO4_A[1], 261 GPIO4_A[2], 262 GPIO4_A[4]
part K pins: 1 GND, 2 GND, 21 GND, 22 GND, 27 GND, 28 GND, 31 GND, 34 GND, 37 GND, 40 GND, 42 GND, 44 GND, 76 GND, 77 GND, 87 GND, 89 GND, 90 GND, 92 GND, 94 GND, 99 GND, 100 GND, 101 GND, 102 GND, 112 GND, 114 GND, 125 GND, 134 GND, 147 GND, 164 GND, 168 GND, 199 GND, 200 GND, 201 GND, 202 GND, 226 GND, 233 GND, 263 GND, 265 GND, 275 VCC_CON, 276 TopBoard_DET0, 277 GND, 278 VB, 279 GND, 280 VCC18, 281 GND, 282 VCC25, 283 GND, 284 VCCA, 285 GND, 286 VCC, 287 GND, 288 GND, 289 VDD, 290 VDD, 291 VDD, 292 VDD, 293 GND, 294 GND, 295 VCCDR, 296 VCCDR, 297 VCCDR, 298 VCCDR, 299 GND, 300 GND, 301 GND, 302 GND, 303 GND, 304 GND, 306 GND, 308 GND, 310 GND, 312 GND, 314 GND, 316 GND, 318 GND, 320 GND, 322 GND, 324 GND, 326 GND, 328 GND, 330 GND, 332 GND, 334 GND, 336 GND, 338 GND, 340 GND, 342 GND, 344 GND, 346 GND, 348 GND, 350 GND, 352 GND, 354 GND, 356 GND, 358 GND, 360 GND, 361 GND, 362 GND, 375 GND, 377 GND, 379 GND, 381 GND, 383 GND, 384 GND, 385 GND, 399 GND, 400 GND

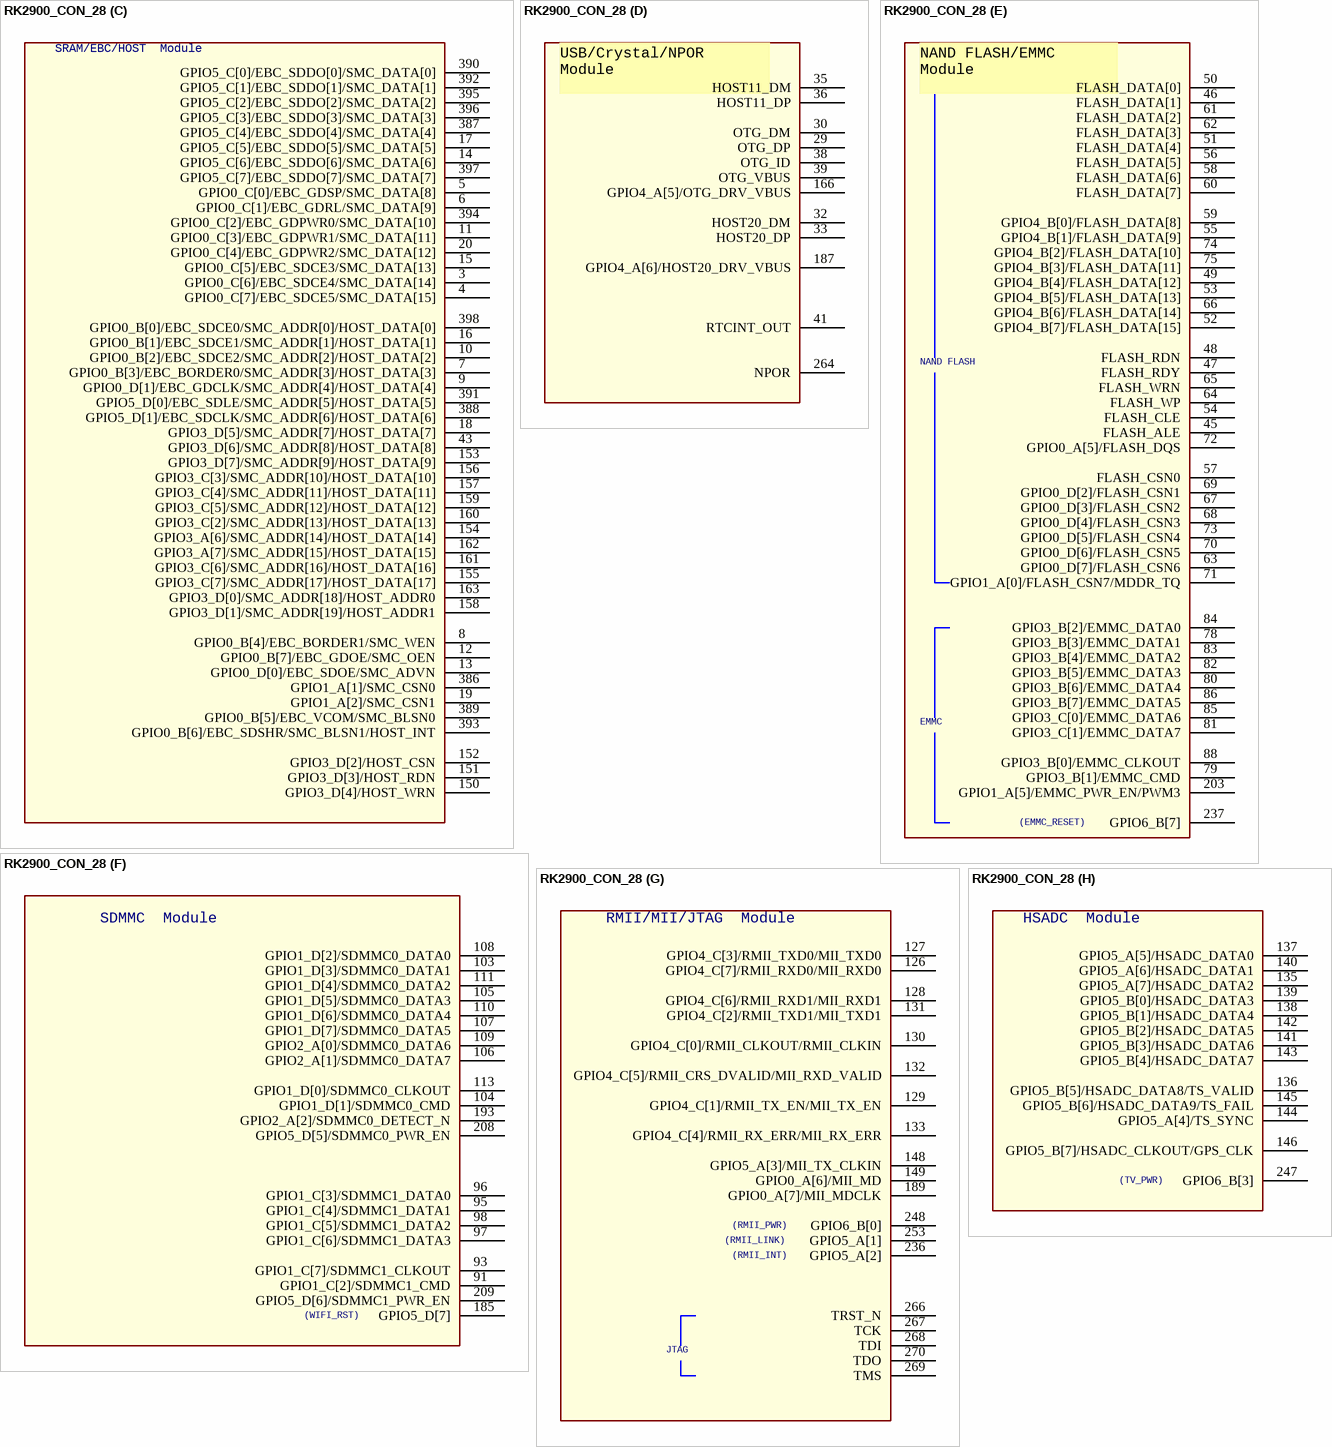
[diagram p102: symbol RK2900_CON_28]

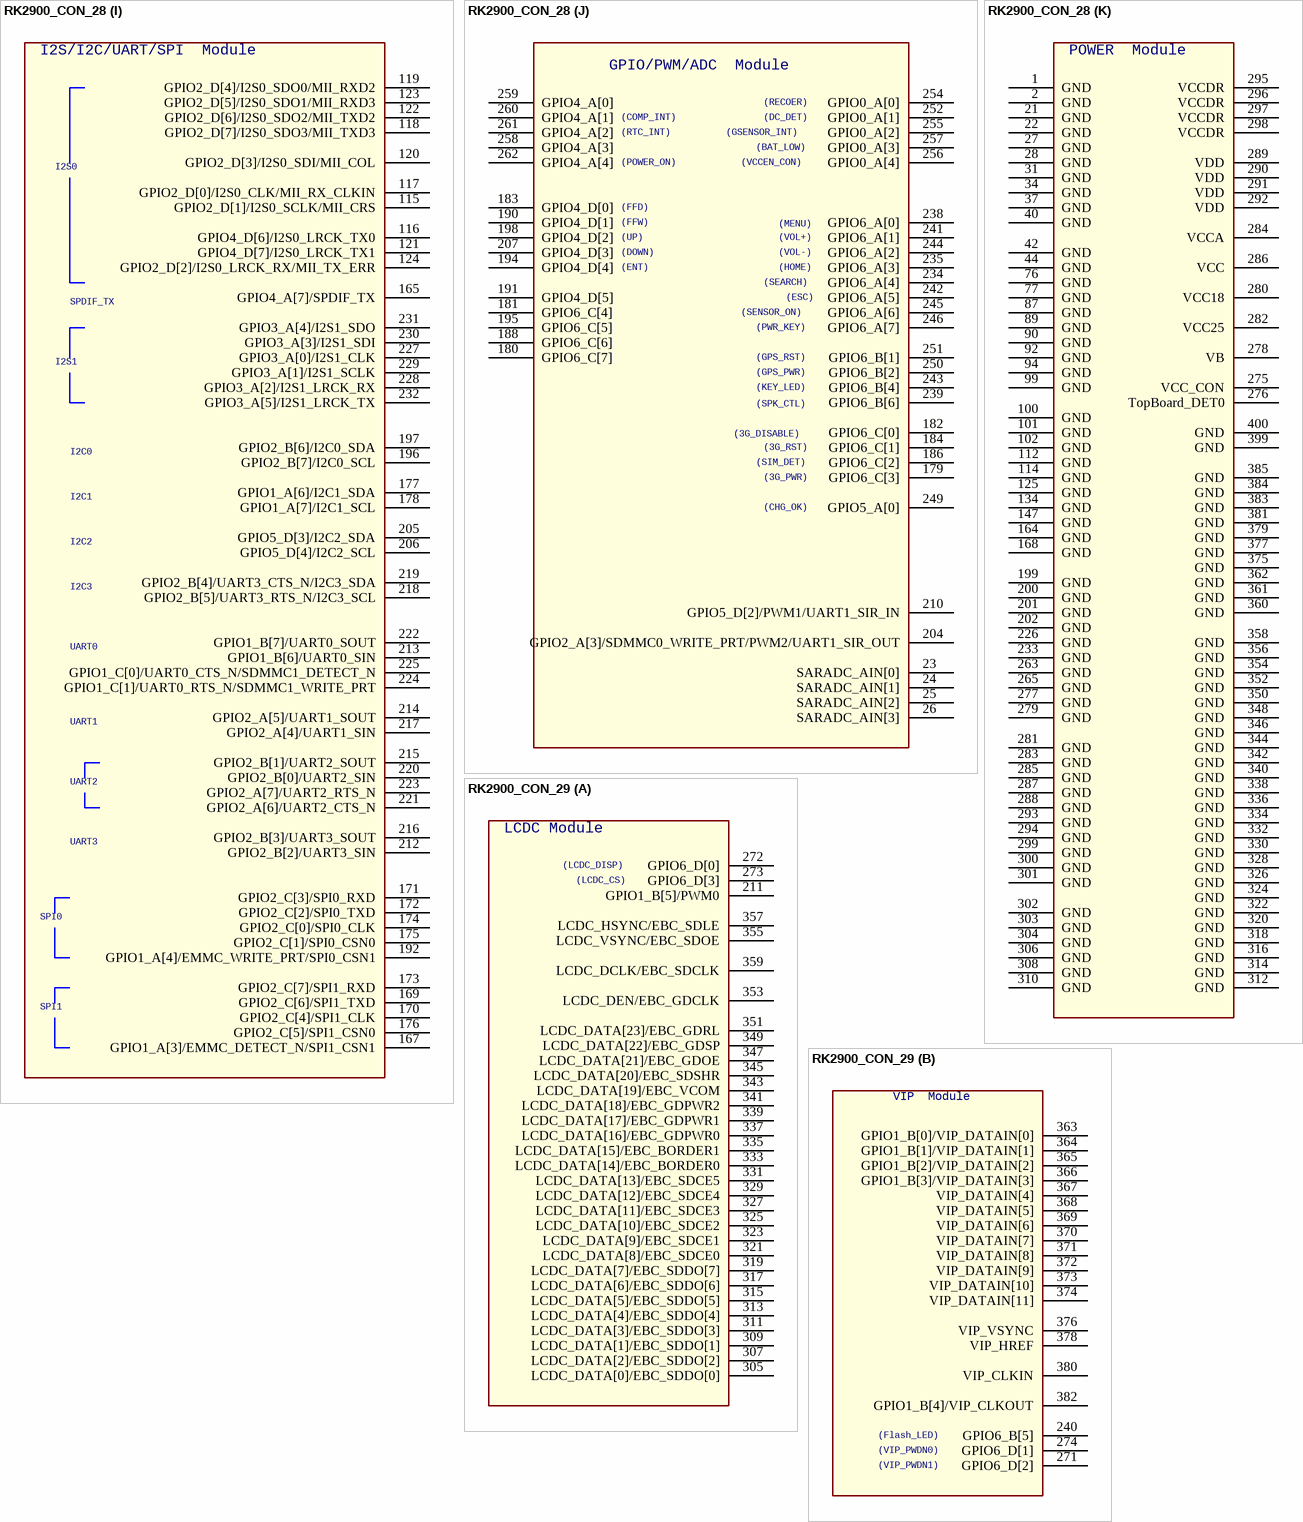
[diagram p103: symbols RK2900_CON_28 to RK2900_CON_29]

## RK2900_CON_28
designator U?
Altium-Right: 160; Altium-Bottom: 390; Altium-Right1: 140; Altium-Bottom1: 270; Altium-Right2: 280; Altium-Bottom2: 520; Altium-Right3: 170; Altium-Bottom3: 240; Altium-Right4: 190; Altium-Bottom4: 530; Altium-Right5: 290; Altium-Bottom5: 300; Altium-Right6: 220; Altium-Bottom6: 340; Altium-Right7: 180; Altium-Bottom7: 200; Altium-Bottom8: 690; Altium-Right9: 250; Altium-Bottom9: 470; Altium-Right10: 120; Altium-Bottom10: 650
footprint RK2900_TOP
part A pins: 211 GPIO1_B[5]/PWM0, 272 GPIO6_D[0], 273 GPIO6_D[3], 305 LCDC_DATA[0]/EBC_SDDO[0], 307 LCDC_DATA[2]/EBC_SDDO[2], 309 LCDC_DATA[1]/EBC_SDDO[1], 311 LCDC_DATA[3]/EBC_SDDO[3], 313 LCDC_DATA[4]/EBC_SDDO[4], 315 LCDC_DATA[5]/EBC_SDDO[5], 317 LCDC_DATA[6]/EBC_SDDO[6], 319 LCDC_DATA[7]/EBC_SDDO[7], 321 LCDC_DATA[8]/EBC_SDCE0, 323 LCDC_DATA[9]/EBC_SDCE1, 325 LCDC_DATA[10]/EBC_SDCE2, 327 LCDC_DATA[11]/EBC_SDCE3, 329 LCDC_DATA[12]/EBC_SDCE4, 331 LCDC_DATA[13]/EBC_SDCE5, 333 LCDC_DATA[14]/EBC_BORDER0, 335 LCDC_DATA[15]/EBC_BORDER1, 337 LCDC_DATA[16]/EBC_GDPWR0, 339 LCDC_DATA[17]/EBC_GDPWR1, 341 LCDC_DATA[18]/EBC_GDPWR2, 343 LCDC_DATA[19]/EBC_VCOM, 345 LCDC_DATA[20]/EBC_SDSHR, 347 LCDC_DATA[21]/EBC_GDOE, 349 LCDC_DATA[22]/EBC_GDSP, 351 LCDC_DATA[23]/EBC_GDRL, 353 LCDC_DEN/EBC_GDCLK, 355 LCDC_VSYNC/EBC_SDOE, 357 LCDC_HSYNC/EBC_SDLE, 359 LCDC_DCLK/EBC_SDCLK
part B pins: 240 GPIO6_B[5], 271 GPIO6_D[2], 274 GPIO6_D[1], 363 GPIO1_B[0]/VIP_DATAIN[0], 364 GPIO1_B[1]/VIP_DATAIN[1], 365 GPIO1_B[2]/VIP_DATAIN[2], 366 GPIO1_B[3]/VIP_DATAIN[3], 367 VIP_DATAIN[4], 368 VIP_DATAIN[5], 369 VIP_DATAIN[6], 370 VIP_DATAIN[7], 371 VIP_DATAIN[8], 372 VIP_DATAIN[9], 373 VIP_DATAIN[10], 374 VIP_DATAIN[11], 376 VIP_VSYNC, 378 VIP_HREF, 380 VIP_CLKIN, 382 GPIO1_B[4]/VIP_CLKOUT
part C pins: 3 GPIO0_C[6]/EBC_SDCE4/SMC_DATA[14], 4 GPIO0_C[7]/EBC_SDCE5/SMC_DATA[15], 5 GPIO0_C[0]/EBC_GDSP/SMC_DATA[8], 6 GPIO0_C[1]/EBC_GDRL/SMC_DATA[9], 7 GPIO0_B[3]/EBC_BORDER0/SMC_ADDR[3]/HOST_DATA[3], 8 GPIO0_B[4]/EBC_BORDER1/SMC_WEN, 9 GPIO0_D[1]/EBC_GDCLK/SMC_ADDR[4]/HOST_DATA[4], 10 GPIO0_B[2]/EBC_SDCE2/SMC_ADDR[2]/HOST_DATA[2], 11 GPIO0_C[3]/EBC_GDPWR1/SMC_DATA[11], 12 GPIO0_B[7]/EBC_GDOE/SMC_OEN, 13 GPIO0_D[0]/EBC_SDOE/SMC_ADVN, 14 GPIO5_C[6]/EBC_SDDO[6]/SMC_DATA[6], 15 GPIO0_C[5]/EBC_SDCE3/SMC_DATA[13], 16 GPIO0_B[1]/EBC_SDCE1/SMC_ADDR[1]/HOST_DATA[1], 17 GPIO5_C[5]/EBC_SDDO[5]/SMC_DATA[5], 18 GPIO3_D[5]/SMC_ADDR[7]/HOST_DATA[7], 19 GPIO1_A[2]/SMC_CSN1, 20 GPIO0_C[4]/EBC_GDPWR2/SMC_DATA[12], 43 GPIO3_D[6]/SMC_ADDR[8]/HOST_DATA[8], 150 GPIO3_D[4]/HOST_WRN, 151 GPIO3_D[3]/HOST_RDN, 152 GPIO3_D[2]/HOST_CSN, 153 GPIO3_D[7]/SMC_ADDR[9]/HOST_DATA[9], 154 GPIO3_A[6]/SMC_ADDR[14]/HOST_DATA[14], 155 GPIO3_C[7]/SMC_ADDR[17]/HOST_DATA[17], 156 GPIO3_C[3]/SMC_ADDR[10]/HOST_DATA[10], 157 GPIO3_C[4]/SMC_ADDR[11]/HOST_DATA[11], 158 GPIO3_D[1]/SMC_ADDR[19]/HOST_ADDR1, 159 GPIO3_C[5]/SMC_ADDR[12]/HOST_DATA[12], 160 GPIO3_C[2]/SMC_ADDR[13]/HOST_DATA[13], 161 GPIO3_C[6]/SMC_ADDR[16]/HOST_DATA[16], 162 GPIO3_A[7]/SMC_ADDR[15]/HOST_DATA[15], 163 GPIO3_D[0]/SMC_ADDR[18]/HOST_ADDR0, 386 GPIO1_A[1]/SMC_CSN0, 387 GPIO5_C[4]/EBC_SDDO[4]/SMC_DATA[4], 388 GPIO5_D[1]/EBC_SDCLK/SMC_ADDR[6]/HOST_DATA[6], 389 GPIO0_B[5]/EBC_VCOM/SMC_BLSN0, 390 GPIO5_C[0]/EBC_SDDO[0]/SMC_DATA[0], 391 GPIO5_D[0]/EBC_SDLE/SMC_ADDR[5]/HOST_DATA[5], 392 GPIO5_C[1]/EBC_SDDO[1]/SMC_DATA[1], 393 GPIO0_B[6]/EBC_SDSHR/SMC_BLSN1/HOST_INT, 394 GPIO0_C[2]/EBC_GDPWR0/SMC_DATA[10], 395 GPIO5_C[2]/EBC_SDDO[2]/SMC_DATA[2], 396 GPIO5_C[3]/EBC_SDDO[3]/SMC_DATA[3], 397 GPIO5_C[7]/EBC_SDDO[7]/SMC_DATA[7], 398 GPIO0_B[0]/EBC_SDCE0/SMC_ADDR[0]/HOST_DATA[0]
part D pins: 29 OTG_DP, 30 OTG_DM, 32 HOST20_DM, 33 HOST20_DP, 35 HOST11_DM, 36 HOST11_DP, 38 OTG_ID, 39 OTG_VBUS, 41 RTCINT_OUT, 166 GPIO4_A[5]/OTG_DRV_VBUS, 187 GPIO4_A[6]/HOST20_DRV_VBUS, 264 NPOR
part E pins: 45 FLASH_ALE, 46 FLASH_DATA[1], 47 FLASH_RDY, 48 FLASH_RDN, 49 GPIO4_B[4]/FLASH_DATA[12], 50 FLASH_DATA[0], 51 FLASH_DATA[4], 52 GPIO4_B[7]/FLASH_DATA[15], 53 GPIO4_B[5]/FLASH_DATA[13], 54 FLASH_CLE, 55 GPIO4_B[1]/FLASH_DATA[9], 56 FLASH_DATA[5], 57 FLASH_CSN0, 58 FLASH_DATA[6], 59 GPIO4_B[0]/FLASH_DATA[8], 60 FLASH_DATA[7], 61 FLASH_DATA[2], 62 FLASH_DATA[3], 63 GPIO0_D[7]/FLASH_CSN6, 64 FLASH_WP, 65 FLASH_WRN, 66 GPIO4_B[6]/FLASH_DATA[14], 67 GPIO0_D[3]/FLASH_CSN2, 68 GPIO0_D[4]/FLASH_CSN3, 69 GPIO0_D[2]/FLASH_CSN1, 70 GPIO0_D[6]/FLASH_CSN5, 71 GPIO1_A[0]/FLASH_CSN7/MDDR_TQ, 72 GPIO0_A[5]/FLASH_DQS, 73 GPIO0_D[5]/FLASH_CSN4, 74 GPIO4_B[2]/FLASH_DATA[10], 75 GPIO4_B[3]/FLASH_DATA[11], 78 GPIO3_B[3]/EMMC_DATA1, 79 GPIO3_B[1]/EMMC_CMD, 80 GPIO3_B[6]/EMMC_DATA4, 81 GPIO3_C[1]/EMMC_DATA7, 82 GPIO3_B[5]/EMMC_DATA3, 83 GPIO3_B[4]/EMMC_DATA2, 84 GPIO3_B[2]/EMMC_DATA0, 85 GPIO3_C[0]/EMMC_DATA6, 86 GPIO3_B[7]/EMMC_DATA5, 88 GPIO3_B[0]/EMMC_CLKOUT, 203 GPIO1_A[5]/EMMC_PWR_EN/PWM3, 237 GPIO6_B[7]
part F pins: 91 GPIO1_C[2]/SDMMC1_CMD, 93 GPIO1_C[7]/SDMMC1_CLKOUT, 95 GPIO1_C[4]/SDMMC1_DATA1, 96 GPIO1_C[3]/SDMMC1_DATA0, 97 GPIO1_C[6]/SDMMC1_DATA3, 98 GPIO1_C[5]/SDMMC1_DATA2, 103 GPIO1_D[3]/SDMMC0_DATA1, 104 GPIO1_D[1]/SDMMC0_CMD, 105 GPIO1_D[5]/SDMMC0_DATA3, 106 GPIO2_A[1]/SDMMC0_DATA7, 107 GPIO1_D[7]/SDMMC0_DATA5, 108 GPIO1_D[2]/SDMMC0_DATA0, 109 GPIO2_A[0]/SDMMC0_DATA6, 110 GPIO1_D[6]/SDMMC0_DATA4, 111 GPIO1_D[4]/SDMMC0_DATA2, 113 GPIO1_D[0]/SDMMC0_CLKOUT, 185 GPIO5_D[7], 193 GPIO2_A[2]/SDMMC0_DETECT_N, 208 GPIO5_D[5]/SDMMC0_PWR_EN, 209 GPIO5_D[6]/SDMMC1_PWR_EN
part G pins: 126 GPIO4_C[7]/RMII_RXD0/MII_RXD0, 127 GPIO4_C[3]/RMII_TXD0/MII_TXD0, 128 GPIO4_C[6]/RMII_RXD1/MII_RXD1, 129 GPIO4_C[1]/RMII_TX_EN/MII_TX_EN, 130 GPIO4_C[0]/RMII_CLKOUT/RMII_CLKIN, 131 GPIO4_C[2]/RMII_TXD1/MII_TXD1, 132 GPIO4_C[5]/RMII_CRS_DVALID/MII_RXD_VALID, 133 GPIO4_C[4]/RMII_RX_ERR/MII_RX_ERR, 148 GPIO5_A[3]/MII_TX_CLKIN, 149 GPIO0_A[6]/MII_MD, 189 GPIO0_A[7]/MII_MDCLK, 236 GPIO5_A[2], 248 GPIO6_B[0], 253 GPIO5_A[1], 266 TRST_N, 267 TCK, 268 TDI, 269 TMS, 270 TDO
part H pins: 135 GPIO5_A[7]/HSADC_DATA2, 136 GPIO5_B[5]/HSADC_DATA8/TS_VALID, 137 GPIO5_A[5]/HSADC_DATA0, 138 GPIO5_B[1]/HSADC_DATA4, 139 GPIO5_B[0]/HSADC_DATA3, 140 GPIO5_A[6]/HSADC_DATA1, 141 GPIO5_B[3]/HSADC_DATA6, 142 GPIO5_B[2]/HSADC_DATA5, 143 GPIO5_B[4]/HSADC_DATA7, 144 GPIO5_A[4]/TS_SYNC, 145 GPIO5_B[6]/HSADC_DATA9/TS_FAIL, 146 GPIO5_B[7]/HSADC_CLKOUT/GPS_CLK, 247 GPIO6_B[3]
part I pins: 115 GPIO2_D[1]/I2S0_SCLK/MII_CRS, 116 GPIO4_D[6]/I2S0_LRCK_TX0, 117 GPIO2_D[0]/I2S0_CLK/MII_RX_CLKIN, 118 GPIO2_D[7]/I2S0_SDO3/MII_TXD3, 119 GPIO2_D[4]/I2S0_SDO0/MII_RXD2, 120 GPIO2_D[3]/I2S0_SDI/MII_COL, 121 GPIO4_D[7]/I2S0_LRCK_TX1, 122 GPIO2_D[6]/I2S0_SDO2/MII_TXD2, 123 GPIO2_D[5]/I2S0_SDO1/MII_RXD3, 124 GPIO2_D[2]/I2S0_LRCK_RX/MII_TX_ERR, 165 GPIO4_A[7]/SPDIF_TX, 167 GPIO1_A[3]/EMMC_DETECT_N/SPI1_CSN1, 169 GPIO2_C[6]/SPI1_TXD, 170 GPIO2_C[4]/SPI1_CLK, 171 GPIO2_C[3]/SPI0_RXD, 172 GPIO2_C[2]/SPI0_TXD, 173 GPIO2_C[7]/SPI1_RXD, 174 GPIO2_C[0]/SPI0_CLK, 175 GPIO2_C[1]/SPI0_CSN0, 176 GPIO2_C[5]/SPI1_CSN0, 177 GPIO1_A[6]/I2C1_SDA, 178 GPIO1_A[7]/I2C1_SCL, 192 GPIO1_A[4]/EMMC_WRITE_PRT/SPI0_CSN1, 196 GPIO2_B[7]/I2C0_SCL, 197 GPIO2_B[6]/I2C0_SDA, 205 GPIO5_D[3]/I2C2_SDA, 206 GPIO5_D[4]/I2C2_SCL, 212 GPIO2_B[2]/UART3_SIN, 213 GPIO1_B[6]/UART0_SIN, 214 GPIO2_A[5]/UART1_SOUT, 215 GPIO2_B[1]/UART2_SOUT, 216 GPIO2_B[3]/UART3_SOUT, 217 GPIO2_A[4]/UART1_SIN, 218 GPIO2_B[5]/UART3_RTS_N/I2C3_SCL, 219 GPIO2_B[4]/UART3_CTS_N/I2C3_SDA, 220 GPIO2_B[0]/UART2_SIN, 221 GPIO2_A[6]/UART2_CTS_N, 222 GPIO1_B[7]/UART0_SOUT, 223 GPIO2_A[7]/UART2_RTS_N, 224 GPIO1_C[1]/UART0_RTS_N/SDMMC1_WRITE_PRT, 225 GPIO1_C[0]/UART0_CTS_N/SDMMC1_DETECT_N, 227 GPIO3_A[0]/I2S1_CLK, 228 GPIO3_A[2]/I2S1_LRCK_RX, 229 GPIO3_A[1]/I2S1_SCLK, 230 GPIO3_A[3]/I2S1_SDI, 231 GPIO3_A[4]/I2S1_SDO, 232 GPIO3_A[5]/I2S1_LRCK_TX
part J pins: 23 SARADC_AIN[0], 24 SARADC_AIN[1], 25 SARADC_AIN[2], 26 SARADC_AIN[3], 179 GPIO6_C[3], 180 GPIO6_C[7], 181 GPIO6_C[4], 182 GPIO6_C[0], 183 GPIO4_D[0], 184 GPIO6_C[1], 186 GPIO6_C[2], 188 GPIO6_C[6], 190 GPIO4_D[1], 191 GPIO4_D[5], 194 GPIO4_D[4], 195 GPIO6_C[5], 198 GPIO4_D[2], 204 GPIO2_A[3]/SDMMC0_WRITE_PRT/PWM2/UART1_SIR_OUT, 207 GPIO4_D[3], 210 GPIO5_D[2]/PWM1/UART1_SIR_IN, 234 GPIO6_A[4], 235 GPIO6_A[3], 238 GPIO6_A[0], 239 GPIO6_B[6], 241 GPIO6_A[1], 242 GPIO6_A[5], 243 GPIO6_B[4], 244 GPIO6_A[2], 245 GPIO6_A[6], 246 GPIO6_A[7], 249 GPIO5_A[0], 250 GPIO6_B[2], 251 GPIO6_B[1], 252 GPIO0_A[1], 254 GPIO0_A[0], 255 GPIO0_A[2], 256 GPIO0_A[4], 257 GPIO0_A[3], 258 GPIO4_A[3], 259 GPIO4_A[0], 260 GPIO4_A[1], 261 GPIO4_A[2], 262 GPIO4_A[4]
part K pins: 1 GND, 2 GND, 21 GND, 22 GND, 27 GND, 28 GND, 31 GND, 34 GND, 37 GND, 40 GND, 42 GND, 44 GND, 76 GND, 77 GND, 87 GND, 89 GND, 90 GND, 92 GND, 94 GND, 99 GND, 100 GND, 101 GND, 102 GND, 112 GND, 114 GND, 125 GND, 134 GND, 147 GND, 164 GND, 168 GND, 199 GND, 200 GND, 201 GND, 202 GND, 226 GND, 233 GND, 263 GND, 265 GND, 275 VCC_CON, 276 TopBoard_DET0, 277 GND, 278 VB, 279 GND, 280 VCC18, 281 GND, 282 VCC25, 283 GND, 284 VCCA, 285 GND, 286 VCC, 287 GND, 288 GND, 289 VDD, 290 VDD, 291 VDD, 292 VDD, 293 GND, 294 GND, 295 VCCDR, 296 VCCDR, 297 VCCDR, 298 VCCDR, 299 GND, 300 GND, 301 GND, 302 GND, 303 GND, 304 GND, 306 GND, 308 GND, 310 GND, 312 GND, 314 GND, 316 GND, 318 GND, 320 GND, 322 GND, 324 GND, 326 GND, 328 GND, 330 GND, 332 GND, 334 GND, 336 GND, 338 GND, 340 GND, 342 GND, 344 GND, 346 GND, 348 GND, 350 GND, 352 GND, 354 GND, 356 GND, 358 GND, 360 GND, 361 GND, 362 GND, 375 GND, 377 GND, 379 GND, 381 GND, 383 GND, 384 GND, 385 GND, 399 GND, 400 GND

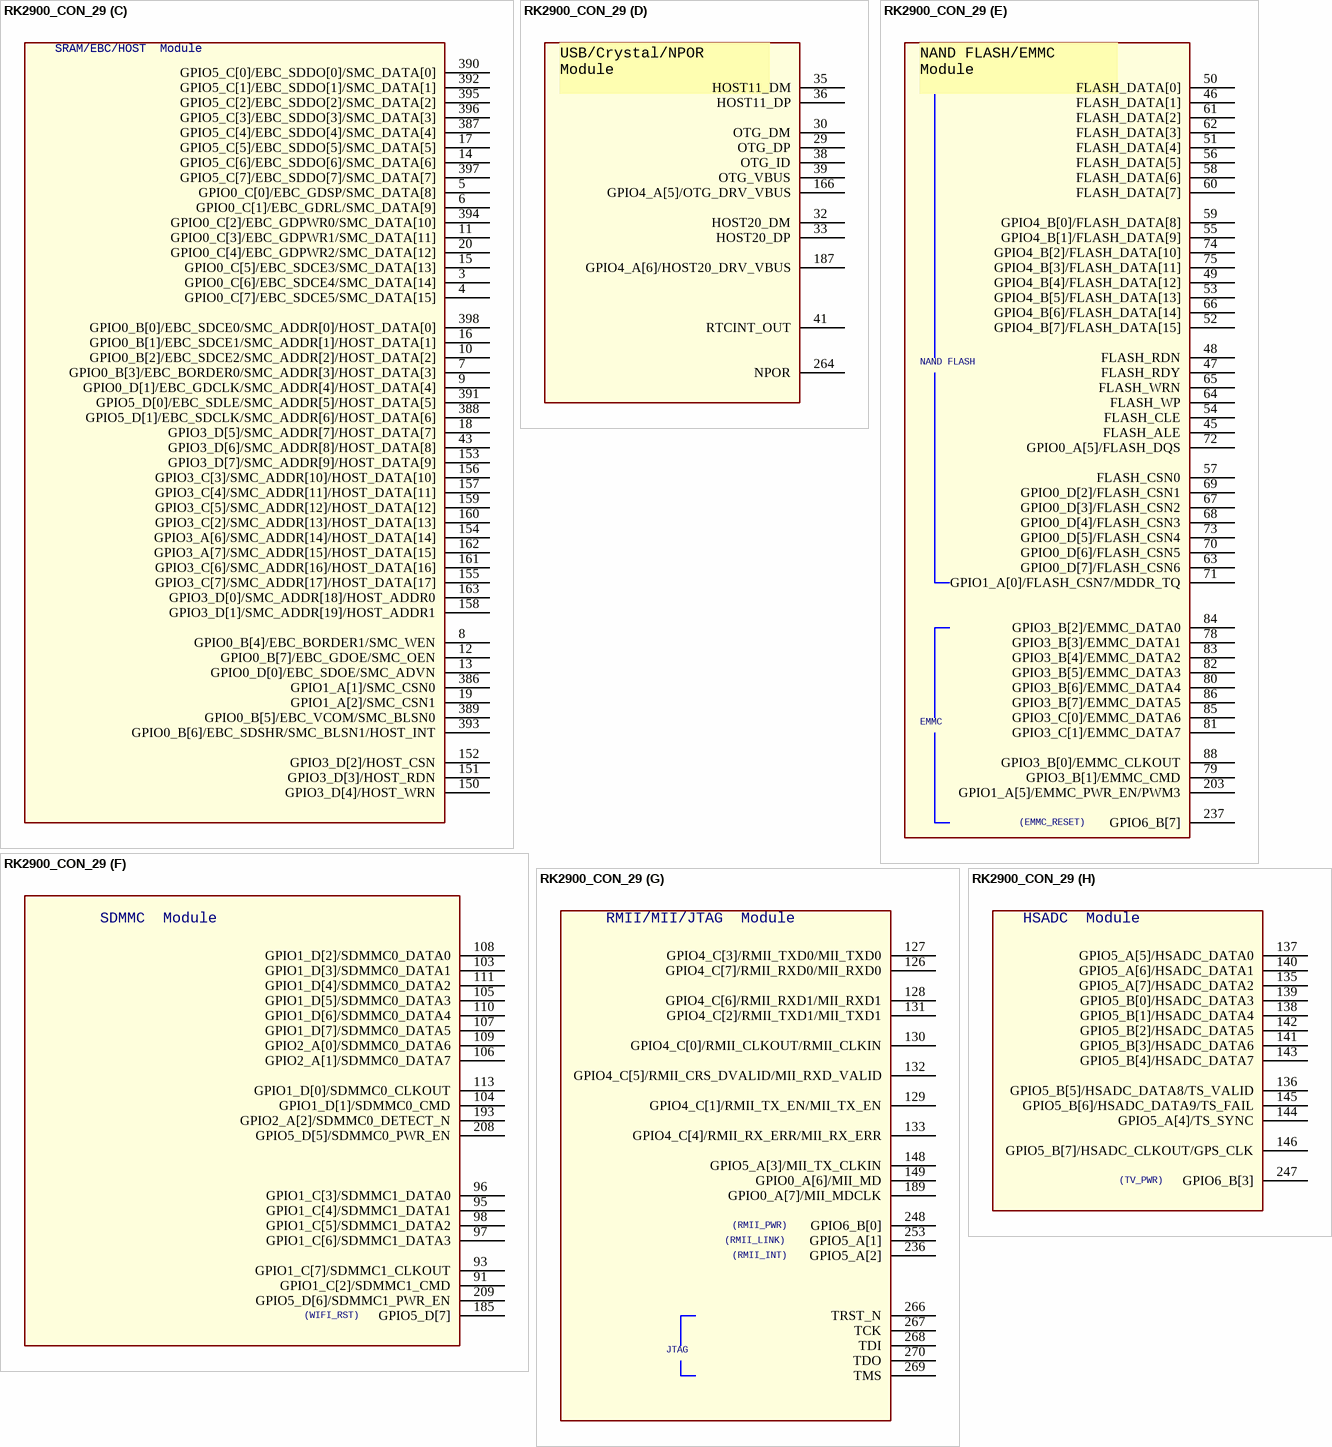
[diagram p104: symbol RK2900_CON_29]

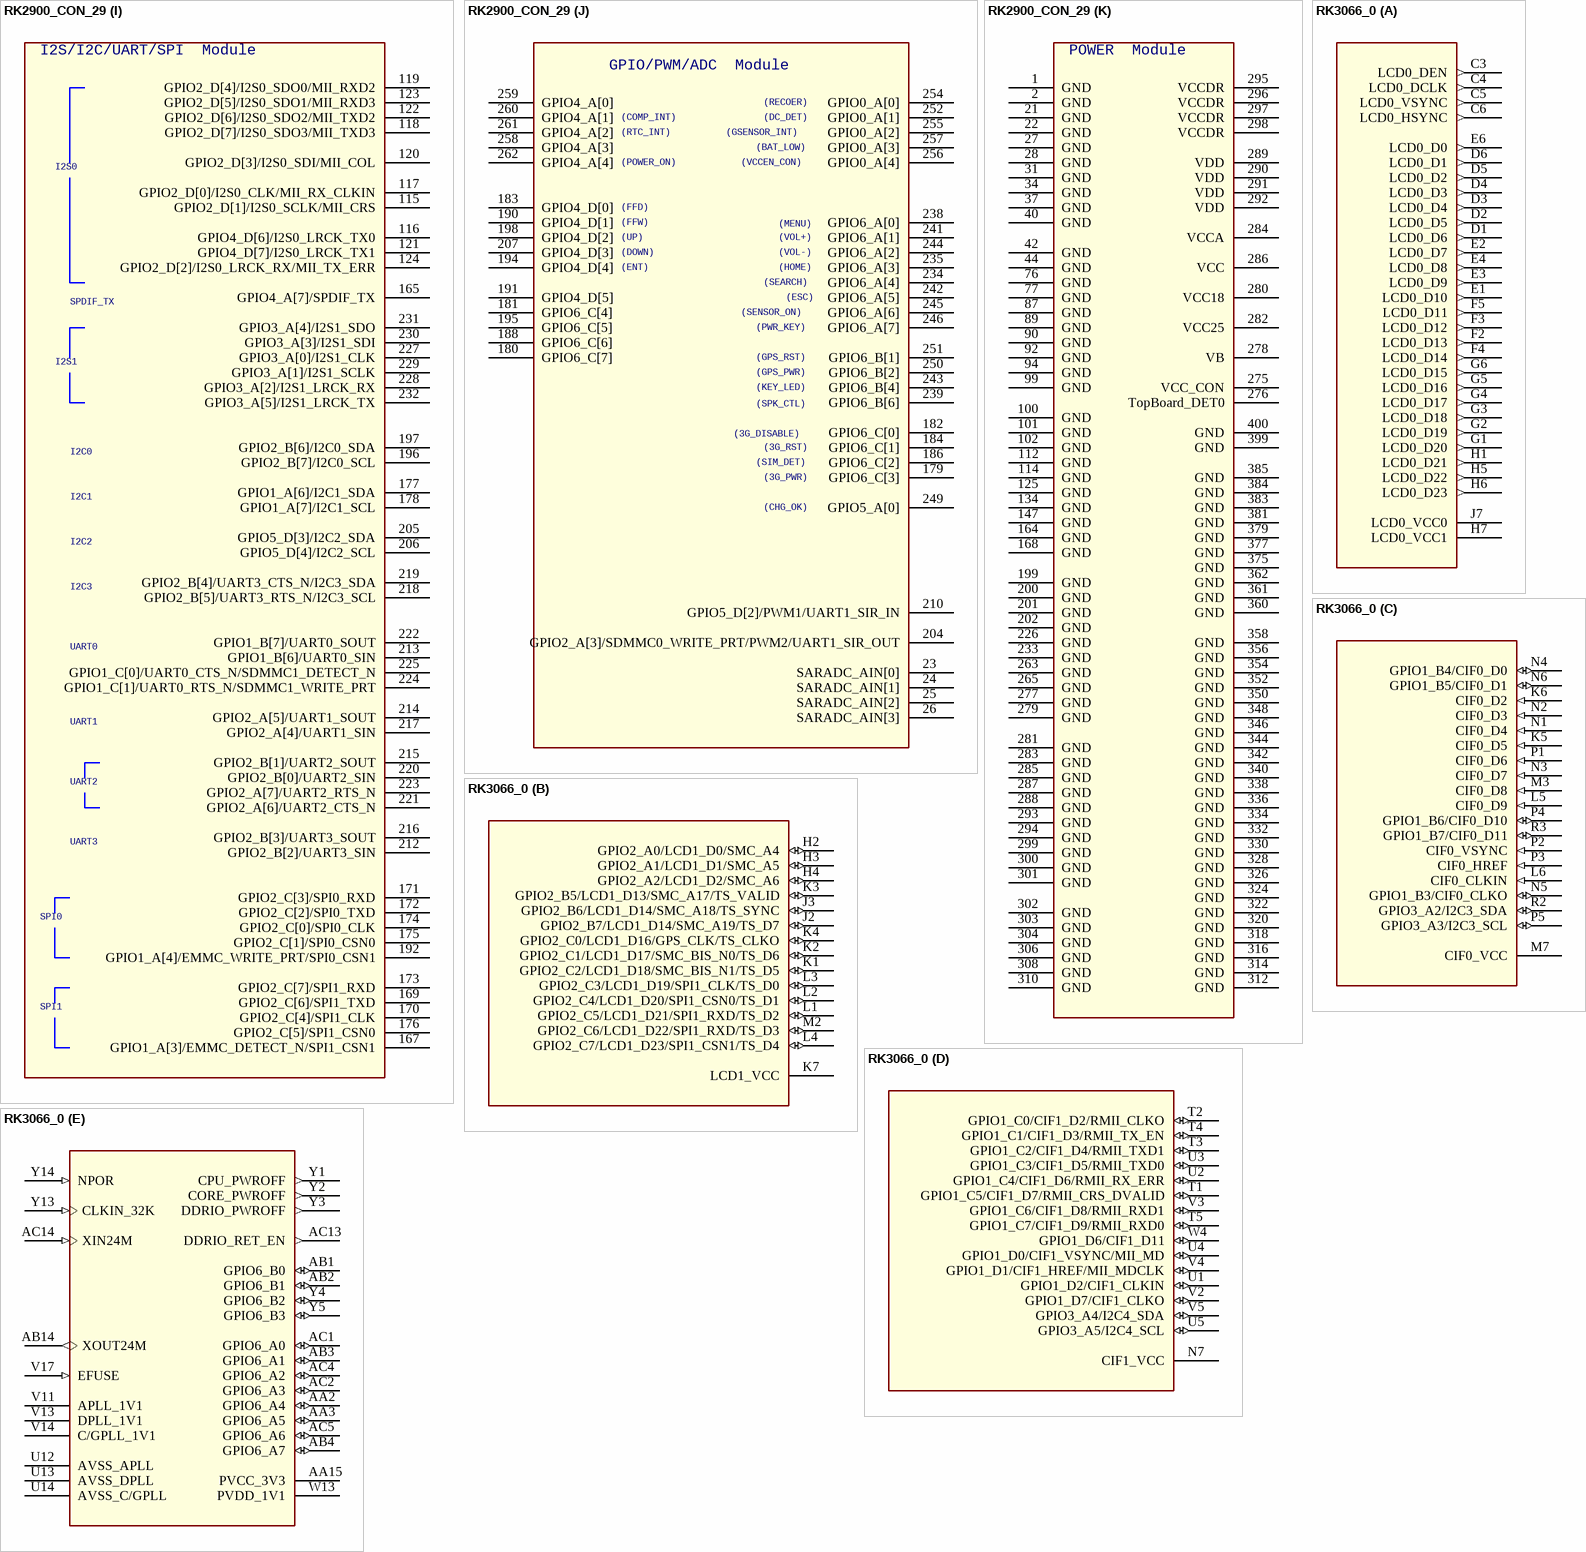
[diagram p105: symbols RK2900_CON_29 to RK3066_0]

## RK2900_CON_29
designator U?
Altium-Right: 160; Altium-Bottom: 390; Altium-Right1: 140; Altium-Bottom1: 270; Altium-Right2: 280; Altium-Bottom2: 520; Altium-Right3: 170; Altium-Bottom3: 240; Altium-Right4: 190; Altium-Bottom4: 530; Altium-Right5: 290; Altium-Bottom5: 300; Altium-Right6: 220; Altium-Bottom6: 340; Altium-Right7: 180; Altium-Bottom7: 200; Altium-Bottom8: 690; Altium-Right9: 250; Altium-Bottom9: 470; Altium-Right10: 120; Altium-Bottom10: 650
footprint RK2900_TOP
part A pins: 211 GPIO1_B[5]/PWM0, 272 GPIO6_D[0], 273 GPIO6_D[3], 305 LCDC_DATA[0]/EBC_SDDO[0], 307 LCDC_DATA[2]/EBC_SDDO[2], 309 LCDC_DATA[1]/EBC_SDDO[1], 311 LCDC_DATA[3]/EBC_SDDO[3], 313 LCDC_DATA[4]/EBC_SDDO[4], 315 LCDC_DATA[5]/EBC_SDDO[5], 317 LCDC_DATA[6]/EBC_SDDO[6], 319 LCDC_DATA[7]/EBC_SDDO[7], 321 LCDC_DATA[8]/EBC_SDCE0, 323 LCDC_DATA[9]/EBC_SDCE1, 325 LCDC_DATA[10]/EBC_SDCE2, 327 LCDC_DATA[11]/EBC_SDCE3, 329 LCDC_DATA[12]/EBC_SDCE4, 331 LCDC_DATA[13]/EBC_SDCE5, 333 LCDC_DATA[14]/EBC_BORDER0, 335 LCDC_DATA[15]/EBC_BORDER1, 337 LCDC_DATA[16]/EBC_GDPWR0, 339 LCDC_DATA[17]/EBC_GDPWR1, 341 LCDC_DATA[18]/EBC_GDPWR2, 343 LCDC_DATA[19]/EBC_VCOM, 345 LCDC_DATA[20]/EBC_SDSHR, 347 LCDC_DATA[21]/EBC_GDOE, 349 LCDC_DATA[22]/EBC_GDSP, 351 LCDC_DATA[23]/EBC_GDRL, 353 LCDC_DEN/EBC_GDCLK, 355 LCDC_VSYNC/EBC_SDOE, 357 LCDC_HSYNC/EBC_SDLE, 359 LCDC_DCLK/EBC_SDCLK
part B pins: 240 GPIO6_B[5], 271 GPIO6_D[2], 274 GPIO6_D[1], 363 GPIO1_B[0]/VIP_DATAIN[0], 364 GPIO1_B[1]/VIP_DATAIN[1], 365 GPIO1_B[2]/VIP_DATAIN[2], 366 GPIO1_B[3]/VIP_DATAIN[3], 367 VIP_DATAIN[4], 368 VIP_DATAIN[5], 369 VIP_DATAIN[6], 370 VIP_DATAIN[7], 371 VIP_DATAIN[8], 372 VIP_DATAIN[9], 373 VIP_DATAIN[10], 374 VIP_DATAIN[11], 376 VIP_VSYNC, 378 VIP_HREF, 380 VIP_CLKIN, 382 GPIO1_B[4]/VIP_CLKOUT
part C pins: 3 GPIO0_C[6]/EBC_SDCE4/SMC_DATA[14], 4 GPIO0_C[7]/EBC_SDCE5/SMC_DATA[15], 5 GPIO0_C[0]/EBC_GDSP/SMC_DATA[8], 6 GPIO0_C[1]/EBC_GDRL/SMC_DATA[9], 7 GPIO0_B[3]/EBC_BORDER0/SMC_ADDR[3]/HOST_DATA[3], 8 GPIO0_B[4]/EBC_BORDER1/SMC_WEN, 9 GPIO0_D[1]/EBC_GDCLK/SMC_ADDR[4]/HOST_DATA[4], 10 GPIO0_B[2]/EBC_SDCE2/SMC_ADDR[2]/HOST_DATA[2], 11 GPIO0_C[3]/EBC_GDPWR1/SMC_DATA[11], 12 GPIO0_B[7]/EBC_GDOE/SMC_OEN, 13 GPIO0_D[0]/EBC_SDOE/SMC_ADVN, 14 GPIO5_C[6]/EBC_SDDO[6]/SMC_DATA[6], 15 GPIO0_C[5]/EBC_SDCE3/SMC_DATA[13], 16 GPIO0_B[1]/EBC_SDCE1/SMC_ADDR[1]/HOST_DATA[1], 17 GPIO5_C[5]/EBC_SDDO[5]/SMC_DATA[5], 18 GPIO3_D[5]/SMC_ADDR[7]/HOST_DATA[7], 19 GPIO1_A[2]/SMC_CSN1, 20 GPIO0_C[4]/EBC_GDPWR2/SMC_DATA[12], 43 GPIO3_D[6]/SMC_ADDR[8]/HOST_DATA[8], 150 GPIO3_D[4]/HOST_WRN, 151 GPIO3_D[3]/HOST_RDN, 152 GPIO3_D[2]/HOST_CSN, 153 GPIO3_D[7]/SMC_ADDR[9]/HOST_DATA[9], 154 GPIO3_A[6]/SMC_ADDR[14]/HOST_DATA[14], 155 GPIO3_C[7]/SMC_ADDR[17]/HOST_DATA[17], 156 GPIO3_C[3]/SMC_ADDR[10]/HOST_DATA[10], 157 GPIO3_C[4]/SMC_ADDR[11]/HOST_DATA[11], 158 GPIO3_D[1]/SMC_ADDR[19]/HOST_ADDR1, 159 GPIO3_C[5]/SMC_ADDR[12]/HOST_DATA[12], 160 GPIO3_C[2]/SMC_ADDR[13]/HOST_DATA[13], 161 GPIO3_C[6]/SMC_ADDR[16]/HOST_DATA[16], 162 GPIO3_A[7]/SMC_ADDR[15]/HOST_DATA[15], 163 GPIO3_D[0]/SMC_ADDR[18]/HOST_ADDR0, 386 GPIO1_A[1]/SMC_CSN0, 387 GPIO5_C[4]/EBC_SDDO[4]/SMC_DATA[4], 388 GPIO5_D[1]/EBC_SDCLK/SMC_ADDR[6]/HOST_DATA[6], 389 GPIO0_B[5]/EBC_VCOM/SMC_BLSN0, 390 GPIO5_C[0]/EBC_SDDO[0]/SMC_DATA[0], 391 GPIO5_D[0]/EBC_SDLE/SMC_ADDR[5]/HOST_DATA[5], 392 GPIO5_C[1]/EBC_SDDO[1]/SMC_DATA[1], 393 GPIO0_B[6]/EBC_SDSHR/SMC_BLSN1/HOST_INT, 394 GPIO0_C[2]/EBC_GDPWR0/SMC_DATA[10], 395 GPIO5_C[2]/EBC_SDDO[2]/SMC_DATA[2], 396 GPIO5_C[3]/EBC_SDDO[3]/SMC_DATA[3], 397 GPIO5_C[7]/EBC_SDDO[7]/SMC_DATA[7], 398 GPIO0_B[0]/EBC_SDCE0/SMC_ADDR[0]/HOST_DATA[0]
part D pins: 29 OTG_DP, 30 OTG_DM, 32 HOST20_DM, 33 HOST20_DP, 35 HOST11_DM, 36 HOST11_DP, 38 OTG_ID, 39 OTG_VBUS, 41 RTCINT_OUT, 166 GPIO4_A[5]/OTG_DRV_VBUS, 187 GPIO4_A[6]/HOST20_DRV_VBUS, 264 NPOR
part E pins: 45 FLASH_ALE, 46 FLASH_DATA[1], 47 FLASH_RDY, 48 FLASH_RDN, 49 GPIO4_B[4]/FLASH_DATA[12], 50 FLASH_DATA[0], 51 FLASH_DATA[4], 52 GPIO4_B[7]/FLASH_DATA[15], 53 GPIO4_B[5]/FLASH_DATA[13], 54 FLASH_CLE, 55 GPIO4_B[1]/FLASH_DATA[9], 56 FLASH_DATA[5], 57 FLASH_CSN0, 58 FLASH_DATA[6], 59 GPIO4_B[0]/FLASH_DATA[8], 60 FLASH_DATA[7], 61 FLASH_DATA[2], 62 FLASH_DATA[3], 63 GPIO0_D[7]/FLASH_CSN6, 64 FLASH_WP, 65 FLASH_WRN, 66 GPIO4_B[6]/FLASH_DATA[14], 67 GPIO0_D[3]/FLASH_CSN2, 68 GPIO0_D[4]/FLASH_CSN3, 69 GPIO0_D[2]/FLASH_CSN1, 70 GPIO0_D[6]/FLASH_CSN5, 71 GPIO1_A[0]/FLASH_CSN7/MDDR_TQ, 72 GPIO0_A[5]/FLASH_DQS, 73 GPIO0_D[5]/FLASH_CSN4, 74 GPIO4_B[2]/FLASH_DATA[10], 75 GPIO4_B[3]/FLASH_DATA[11], 78 GPIO3_B[3]/EMMC_DATA1, 79 GPIO3_B[1]/EMMC_CMD, 80 GPIO3_B[6]/EMMC_DATA4, 81 GPIO3_C[1]/EMMC_DATA7, 82 GPIO3_B[5]/EMMC_DATA3, 83 GPIO3_B[4]/EMMC_DATA2, 84 GPIO3_B[2]/EMMC_DATA0, 85 GPIO3_C[0]/EMMC_DATA6, 86 GPIO3_B[7]/EMMC_DATA5, 88 GPIO3_B[0]/EMMC_CLKOUT, 203 GPIO1_A[5]/EMMC_PWR_EN/PWM3, 237 GPIO6_B[7]
part F pins: 91 GPIO1_C[2]/SDMMC1_CMD, 93 GPIO1_C[7]/SDMMC1_CLKOUT, 95 GPIO1_C[4]/SDMMC1_DATA1, 96 GPIO1_C[3]/SDMMC1_DATA0, 97 GPIO1_C[6]/SDMMC1_DATA3, 98 GPIO1_C[5]/SDMMC1_DATA2, 103 GPIO1_D[3]/SDMMC0_DATA1, 104 GPIO1_D[1]/SDMMC0_CMD, 105 GPIO1_D[5]/SDMMC0_DATA3, 106 GPIO2_A[1]/SDMMC0_DATA7, 107 GPIO1_D[7]/SDMMC0_DATA5, 108 GPIO1_D[2]/SDMMC0_DATA0, 109 GPIO2_A[0]/SDMMC0_DATA6, 110 GPIO1_D[6]/SDMMC0_DATA4, 111 GPIO1_D[4]/SDMMC0_DATA2, 113 GPIO1_D[0]/SDMMC0_CLKOUT, 185 GPIO5_D[7], 193 GPIO2_A[2]/SDMMC0_DETECT_N, 208 GPIO5_D[5]/SDMMC0_PWR_EN, 209 GPIO5_D[6]/SDMMC1_PWR_EN
part G pins: 126 GPIO4_C[7]/RMII_RXD0/MII_RXD0, 127 GPIO4_C[3]/RMII_TXD0/MII_TXD0, 128 GPIO4_C[6]/RMII_RXD1/MII_RXD1, 129 GPIO4_C[1]/RMII_TX_EN/MII_TX_EN, 130 GPIO4_C[0]/RMII_CLKOUT/RMII_CLKIN, 131 GPIO4_C[2]/RMII_TXD1/MII_TXD1, 132 GPIO4_C[5]/RMII_CRS_DVALID/MII_RXD_VALID, 133 GPIO4_C[4]/RMII_RX_ERR/MII_RX_ERR, 148 GPIO5_A[3]/MII_TX_CLKIN, 149 GPIO0_A[6]/MII_MD, 189 GPIO0_A[7]/MII_MDCLK, 236 GPIO5_A[2], 248 GPIO6_B[0], 253 GPIO5_A[1], 266 TRST_N, 267 TCK, 268 TDI, 269 TMS, 270 TDO
part H pins: 135 GPIO5_A[7]/HSADC_DATA2, 136 GPIO5_B[5]/HSADC_DATA8/TS_VALID, 137 GPIO5_A[5]/HSADC_DATA0, 138 GPIO5_B[1]/HSADC_DATA4, 139 GPIO5_B[0]/HSADC_DATA3, 140 GPIO5_A[6]/HSADC_DATA1, 141 GPIO5_B[3]/HSADC_DATA6, 142 GPIO5_B[2]/HSADC_DATA5, 143 GPIO5_B[4]/HSADC_DATA7, 144 GPIO5_A[4]/TS_SYNC, 145 GPIO5_B[6]/HSADC_DATA9/TS_FAIL, 146 GPIO5_B[7]/HSADC_CLKOUT/GPS_CLK, 247 GPIO6_B[3]
part I pins: 115 GPIO2_D[1]/I2S0_SCLK/MII_CRS, 116 GPIO4_D[6]/I2S0_LRCK_TX0, 117 GPIO2_D[0]/I2S0_CLK/MII_RX_CLKIN, 118 GPIO2_D[7]/I2S0_SDO3/MII_TXD3, 119 GPIO2_D[4]/I2S0_SDO0/MII_RXD2, 120 GPIO2_D[3]/I2S0_SDI/MII_COL, 121 GPIO4_D[7]/I2S0_LRCK_TX1, 122 GPIO2_D[6]/I2S0_SDO2/MII_TXD2, 123 GPIO2_D[5]/I2S0_SDO1/MII_RXD3, 124 GPIO2_D[2]/I2S0_LRCK_RX/MII_TX_ERR, 165 GPIO4_A[7]/SPDIF_TX, 167 GPIO1_A[3]/EMMC_DETECT_N/SPI1_CSN1, 169 GPIO2_C[6]/SPI1_TXD, 170 GPIO2_C[4]/SPI1_CLK, 171 GPIO2_C[3]/SPI0_RXD, 172 GPIO2_C[2]/SPI0_TXD, 173 GPIO2_C[7]/SPI1_RXD, 174 GPIO2_C[0]/SPI0_CLK, 175 GPIO2_C[1]/SPI0_CSN0, 176 GPIO2_C[5]/SPI1_CSN0, 177 GPIO1_A[6]/I2C1_SDA, 178 GPIO1_A[7]/I2C1_SCL, 192 GPIO1_A[4]/EMMC_WRITE_PRT/SPI0_CSN1, 196 GPIO2_B[7]/I2C0_SCL, 197 GPIO2_B[6]/I2C0_SDA, 205 GPIO5_D[3]/I2C2_SDA, 206 GPIO5_D[4]/I2C2_SCL, 212 GPIO2_B[2]/UART3_SIN, 213 GPIO1_B[6]/UART0_SIN, 214 GPIO2_A[5]/UART1_SOUT, 215 GPIO2_B[1]/UART2_SOUT, 216 GPIO2_B[3]/UART3_SOUT, 217 GPIO2_A[4]/UART1_SIN, 218 GPIO2_B[5]/UART3_RTS_N/I2C3_SCL, 219 GPIO2_B[4]/UART3_CTS_N/I2C3_SDA, 220 GPIO2_B[0]/UART2_SIN, 221 GPIO2_A[6]/UART2_CTS_N, 222 GPIO1_B[7]/UART0_SOUT, 223 GPIO2_A[7]/UART2_RTS_N, 224 GPIO1_C[1]/UART0_RTS_N/SDMMC1_WRITE_PRT, 225 GPIO1_C[0]/UART0_CTS_N/SDMMC1_DETECT_N, 227 GPIO3_A[0]/I2S1_CLK, 228 GPIO3_A[2]/I2S1_LRCK_RX, 229 GPIO3_A[1]/I2S1_SCLK, 230 GPIO3_A[3]/I2S1_SDI, 231 GPIO3_A[4]/I2S1_SDO, 232 GPIO3_A[5]/I2S1_LRCK_TX
part J pins: 23 SARADC_AIN[0], 24 SARADC_AIN[1], 25 SARADC_AIN[2], 26 SARADC_AIN[3], 179 GPIO6_C[3], 180 GPIO6_C[7], 181 GPIO6_C[4], 182 GPIO6_C[0], 183 GPIO4_D[0], 184 GPIO6_C[1], 186 GPIO6_C[2], 188 GPIO6_C[6], 190 GPIO4_D[1], 191 GPIO4_D[5], 194 GPIO4_D[4], 195 GPIO6_C[5], 198 GPIO4_D[2], 204 GPIO2_A[3]/SDMMC0_WRITE_PRT/PWM2/UART1_SIR_OUT, 207 GPIO4_D[3], 210 GPIO5_D[2]/PWM1/UART1_SIR_IN, 234 GPIO6_A[4], 235 GPIO6_A[3], 238 GPIO6_A[0], 239 GPIO6_B[6], 241 GPIO6_A[1], 242 GPIO6_A[5], 243 GPIO6_B[4], 244 GPIO6_A[2], 245 GPIO6_A[6], 246 GPIO6_A[7], 249 GPIO5_A[0], 250 GPIO6_B[2], 251 GPIO6_B[1], 252 GPIO0_A[1], 254 GPIO0_A[0], 255 GPIO0_A[2], 256 GPIO0_A[4], 257 GPIO0_A[3], 258 GPIO4_A[3], 259 GPIO4_A[0], 260 GPIO4_A[1], 261 GPIO4_A[2], 262 GPIO4_A[4]
part K pins: 1 GND, 2 GND, 21 GND, 22 GND, 27 GND, 28 GND, 31 GND, 34 GND, 37 GND, 40 GND, 42 GND, 44 GND, 76 GND, 77 GND, 87 GND, 89 GND, 90 GND, 92 GND, 94 GND, 99 GND, 100 GND, 101 GND, 102 GND, 112 GND, 114 GND, 125 GND, 134 GND, 147 GND, 164 GND, 168 GND, 199 GND, 200 GND, 201 GND, 202 GND, 226 GND, 233 GND, 263 GND, 265 GND, 275 VCC_CON, 276 TopBoard_DET0, 277 GND, 278 VB, 279 GND, 280 VCC18, 281 GND, 282 VCC25, 283 GND, 284 VCCA, 285 GND, 286 VCC, 287 GND, 288 GND, 289 VDD, 290 VDD, 291 VDD, 292 VDD, 293 GND, 294 GND, 295 VCCDR, 296 VCCDR, 297 VCCDR, 298 VCCDR, 299 GND, 300 GND, 301 GND, 302 GND, 303 GND, 304 GND, 306 GND, 308 GND, 310 GND, 312 GND, 314 GND, 316 GND, 318 GND, 320 GND, 322 GND, 324 GND, 326 GND, 328 GND, 330 GND, 332 GND, 334 GND, 336 GND, 338 GND, 340 GND, 342 GND, 344 GND, 346 GND, 348 GND, 350 GND, 352 GND, 354 GND, 356 GND, 358 GND, 360 GND, 361 GND, 362 GND, 375 GND, 377 GND, 379 GND, 381 GND, 383 GND, 384 GND, 385 GND, 399 GND, 400 GND

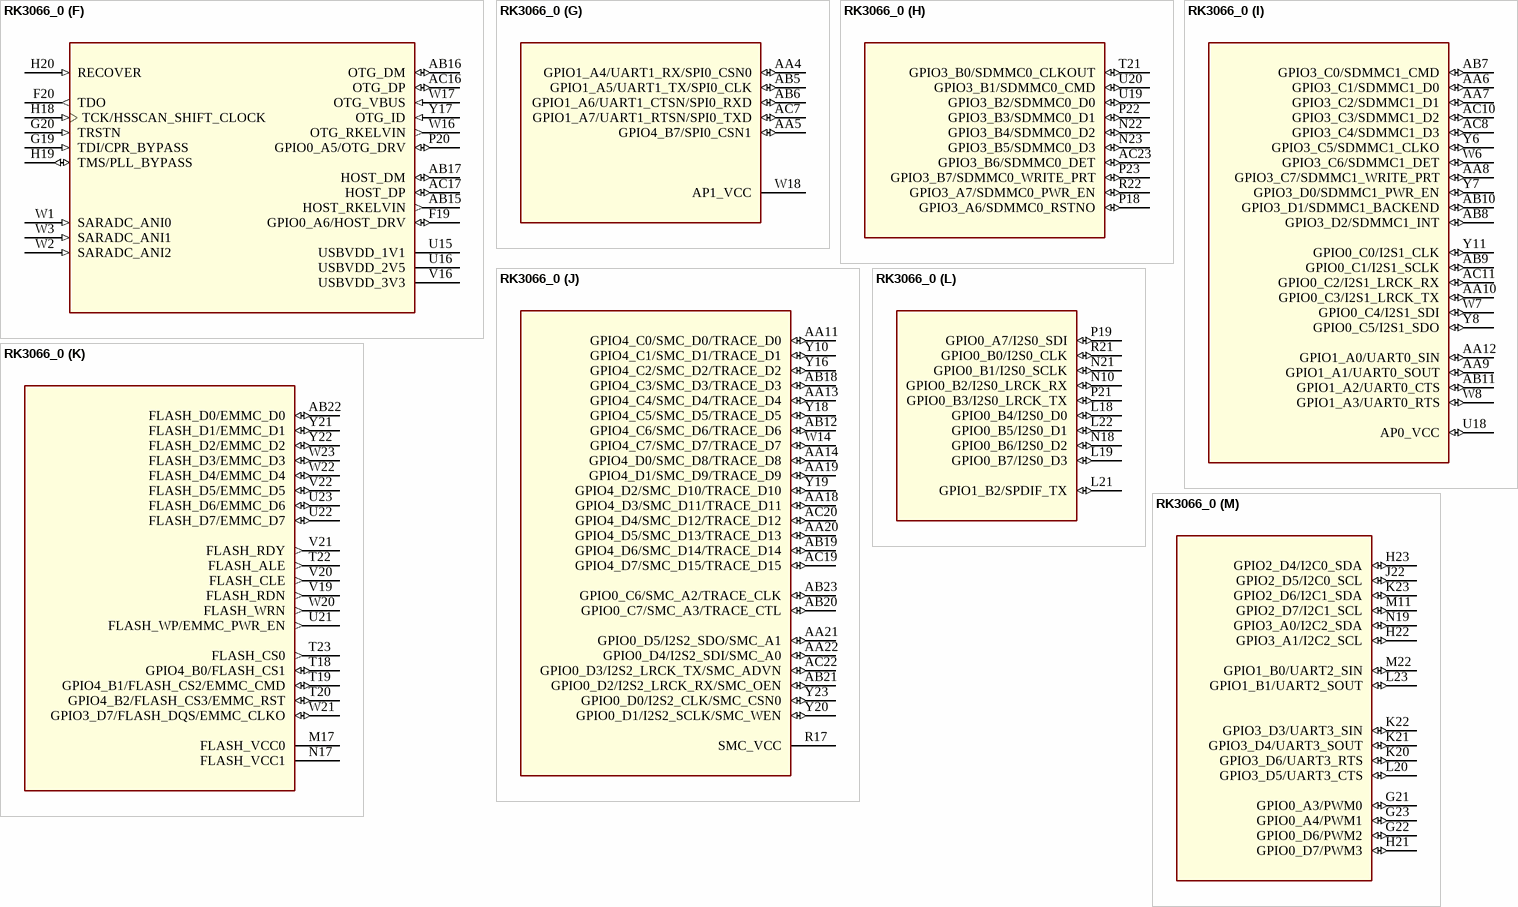
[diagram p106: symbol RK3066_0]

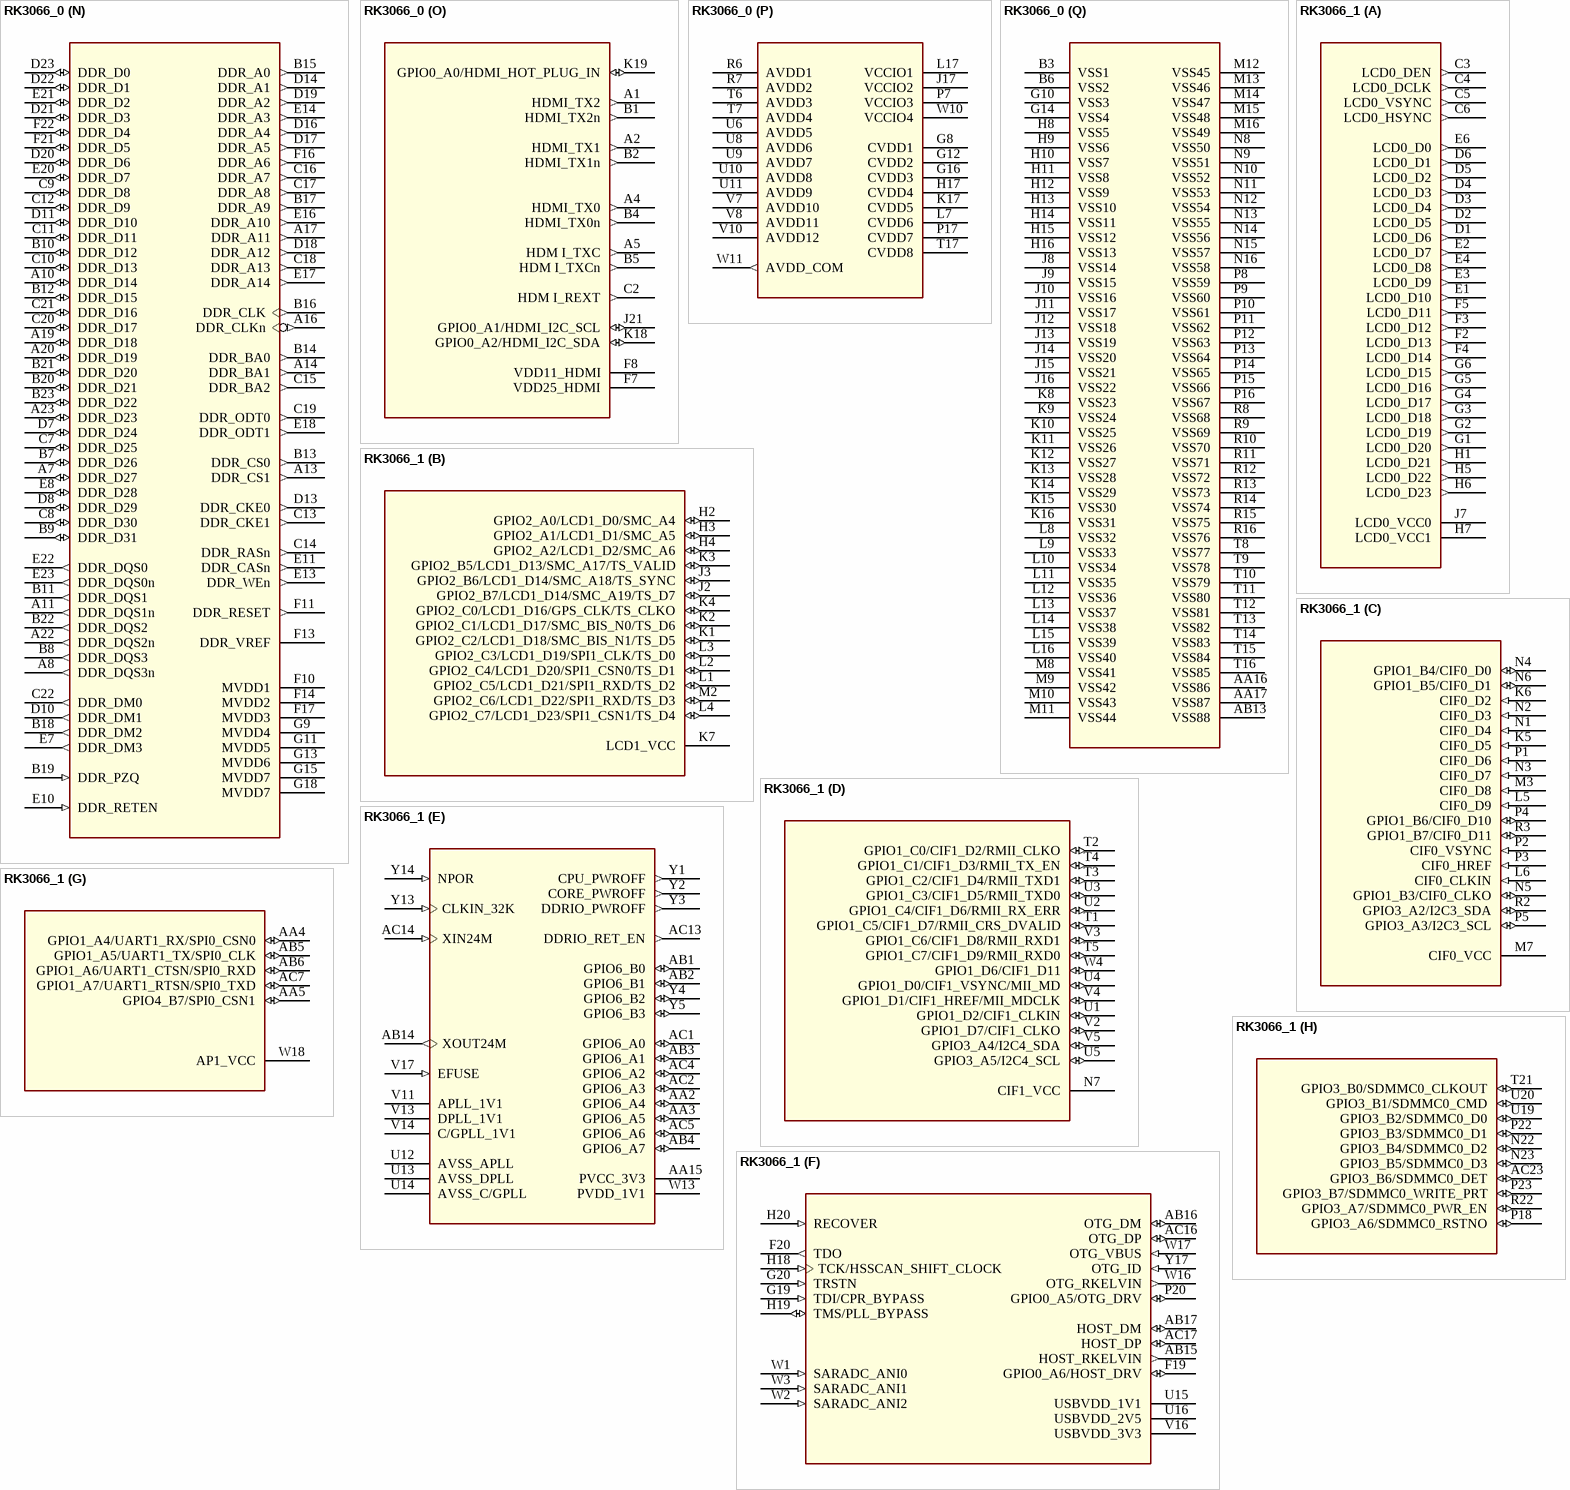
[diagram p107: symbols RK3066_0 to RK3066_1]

## RK3066_0
designator U?
Altium-Right: 80; Altium-Bottom: 350; Altium-Right1: 200; Altium-Bottom1: 190; Altium-Right2: 120; Altium-Bottom2: 230; Altium-Right4: 150; Altium-Bottom4: 250; Altium-Bottom5: 180; Altium-Right6: 160; Altium-Bottom7: 130; Altium-Bottom8: 280; Altium-Bottom9: 310; Altium-Bottom10: 270; Altium-Bottom11: 140; Altium-Bottom13: 530; Altium-Right15: 110; Altium-Bottom15: 170; Altium-Right16: 100; Altium-Bottom16: 470
footprint BGA453
part A pins: C3 LCD0_DEN (out), C4 LCD0_DCLK (out), C5 LCD0_VSYNC (out), C6 LCD0_HSYNC (out), D1 LCD0_D6 (out), D2 LCD0_D5 (out), D3 LCD0_D4 (out), D4 LCD0_D3 (out), D5 LCD0_D2 (out), D6 LCD0_D1 (out), E1 LCD0_D10 (out), E2 LCD0_D7 (out), E3 LCD0_D9 (out), E4 LCD0_D8 (out), E6 LCD0_D0 (out), F2 LCD0_D13 (out), F3 LCD0_D12 (out), F4 LCD0_D14 (out), F5 LCD0_D11 (out), G1 LCD0_D20 (out), G2 LCD0_D19 (out), G3 LCD0_D18 (out), G4 LCD0_D17 (out), G5 LCD0_D16 (out), G6 LCD0_D15 (out), H1 LCD0_D21 (out), H5 LCD0_D22 (out), H6 LCD0_D23 (out), H7 LCD0_VCC1 (power), J7 LCD0_VCC0 (power)
part B pins: H2 GPIO2_A0/LCD1_D0/SMC_A4 (io), H3 GPIO2_A1/LCD1_D1/SMC_A5 (io), H4 GPIO2_A2/LCD1_D2/SMC_A6 (io), J2 GPIO2_B7/LCD1_D14/SMC_A19/TS_D7 (io), J3 GPIO2_B6/LCD1_D14/SMC_A18/TS_SYNC (io), K1 GPIO2_C2/LCD1_D18/SMC_BIS_N1/TS_D5 (io), K2 GPIO2_C1/LCD1_D17/SMC_BIS_N0/TS_D6 (io), K3 GPIO2_B5/LCD1_D13/SMC_A17/TS_VALID (io), K4 GPIO2_C0/LCD1_D16/GPS_CLK/TS_CLKO (io), K7 LCD1_VCC (power), L1 GPIO2_C5/LCD1_D21/SPI1_RXD/TS_D2 (io), L2 GPIO2_C4/LCD1_D20/SPI1_CSN0/TS_D1 (io), L3 GPIO2_C3/LCD1_D19/SPI1_CLK/TS_D0 (io), L4 GPIO2_C7/LCD1_D23/SPI1_CSN1/TS_D4 (io), M2 GPIO2_C6/LCD1_D22/SPI1_RXD/TS_D3 (io)
part C pins: K5 CIF0_D5 (in), K6 CIF0_D2 (in), L5 CIF0_D9 (in), L6 CIF0_CLKIN (in), M3 CIF0_D8 (in), M7 CIF0_VCC (power), N1 CIF0_D4 (in), N2 CIF0_D3 (in), N3 CIF0_D7 (in), N4 GPIO1_B4/CIF0_D0 (io), N5 GPIO1_B3/CIF0_CLKO (io), N6 GPIO1_B5/CIF0_D1 (io), P1 CIF0_D6 (in), P2 CIF0_VSYNC (in), P3 CIF0_HREF (in), P4 GPIO1_B6/CIF0_D10 (io), P5 GPIO3_A3/I2C3_SCL (io), R2 GPIO3_A2/I2C3_SDA (io), R3 GPIO1_B7/CIF0_D11 (io)
part D pins: N7 CIF1_VCC (power), T1 GPIO1_C5/CIF1_D7/RMII_CRS_DVALID (io), T2 GPIO1_C0/CIF1_D2/RMII_CLKO (io), T3 GPIO1_C2/CIF1_D4/RMII_TXD1 (io), T4 GPIO1_C1/CIF1_D3/RMII_TX_EN (io), T5 GPIO1_C7/CIF1_D9/RMII_RXD0 (io), U1 GPIO1_D2/CIF1_CLKIN (io), U2 GPIO1_C4/CIF1_D6/RMII_RX_ERR (io), U3 GPIO1_C3/CIF1_D5/RMII_TXD0 (io), U4 GPIO1_D0/CIF1_VSYNC/MII_MD (io), U5 GPIO3_A5/I2C4_SCL (io), V2 GPIO1_D7/CIF1_CLKO (io), V3 GPIO1_C6/CIF1_D8/RMII_RXD1 (io), V4 GPIO1_D1/CIF1_HREF/MII_MDCLK (io), V5 GPIO3_A4/I2C4_SDA (io), W4 GPIO1_D6/CIF1_D11 (io)
part E pins: AA2 GPIO6_A4 (io), AA3 GPIO6_A5 (io), AA15 PVCC_3V3 (power), AB1 GPIO6_B0 (io), AB2 GPIO6_B1 (io), AB3 GPIO6_A1 (io), AB4 GPIO6_A7 (io), AB14 XOUT24M (out), AC1 GPIO6_A0 (io), AC2 GPIO6_A3 (io), AC4 GPIO6_A2 (io), AC5 GPIO6_A6 (io), AC13 DDRIO_RET_EN (out), AC14 XIN24M (in), U12 AVSS_APLL (power), U13 AVSS_DPLL (power), U14 AVSS_C/GPLL (power), V11 APLL_1V1 (power), V13 DPLL_1V1 (power), V14 C/GPLL_1V1 (power), V17 EFUSE (in), W13 PVDD_1V1 (power), Y1 CPU_PWROFF (out), Y2 CORE_PWROFF (out), Y3 DDRIO_PWROFF (out), Y4 GPIO6_B2 (io), Y5 GPIO6_B3 (io), Y13 CLKIN_32K (in), Y14 NPOR (in)
part F pins: AB15 HOST_RKELVIN (out), AB16 OTG_DM (io), AB17 HOST_DM (io), AC16 OTG_DP (io), AC17 HOST_DP (io), F19 GPIO0_A6/HOST_DRV (io), F20 TDO (out), G19 TDI/CPR_BYPASS (in), G20 TRSTN (in), H18 TCK/HSSCAN_SHIFT_CLOCK (in), H19 TMS/PLL_BYPASS (io), H20 RECOVER (in), P20 GPIO0_A5/OTG_DRV (io), U15 USBVDD_1V1 (power), U16 USBVDD_2V5 (power), V16 USBVDD_3V3 (power), W1 SARADC_ANI0 (in), W2 SARADC_ANI2 (in), W3 SARADC_ANI1 (in), W16 OTG_RKELVIN (out), W17 OTG_VBUS (in), Y17 OTG_ID (in)
part G pins: AA4 GPIO1_A4/UART1_RX/SPI0_CSN0 (io), AA5 GPIO4_B7/SPI0_CSN1 (io), AB5 GPIO1_A5/UART1_TX/SPI0_CLK (io), AB6 GPIO1_A6/UART1_CTSN/SPI0_RXD (io), AC7 GPIO1_A7/UART1_RTSN/SPI0_TXD (io), W18 AP1_VCC (power)
part H pins: AC23 GPIO3_B6/SDMMC0_DET (io), N22 GPIO3_B4/SDMMC0_D2 (io), N23 GPIO3_B5/SDMMC0_D3 (io), P18 GPIO3_A6/SDMMC0_RSTNO (io), P22 GPIO3_B3/SDMMC0_D1 (io), P23 GPIO3_B7/SDMMC0_WRITE_PRT (io), R22 GPIO3_A7/SDMMC0_PWR_EN (io), T21 GPIO3_B0/SDMMC0_CLKOUT (io), U19 GPIO3_B2/SDMMC0_D0 (io), U20 GPIO3_B1/SDMMC0_CMD (io)
part I pins: AA6 GPIO3_C1/SDMMC1_D0 (io), AA7 GPIO3_C2/SDMMC1_D1 (io), AA8 GPIO3_C7/SDMMC1_WRITE_PRT (io), AA9 GPIO1_A1/UART0_SOUT (io), AA10 GPIO0_C3/I2S1_LRCK_TX (io), AA12 GPIO1_A0/UART0_SIN (io), AB7 GPIO3_C0/SDMMC1_CMD (io), AB8 GPIO3_D2/SDMMC1_INT (io), AB9 GPIO0_C1/I2S1_SCLK (io), AB10 GPIO3_D1/SDMMC1_BACKEND (io), AB11 GPIO1_A2/UART0_CTS (io), AC8 GPIO3_C4/SDMMC1_D3 (io), AC10 GPIO3_C3/SDMMC1_D2 (io), AC11 GPIO0_C2/I2S1_LRCK_RX (io), U18 AP0_VCC (io), W6 GPIO3_C6/SDMMC1_DET (io), W7 GPIO0_C4/I2S1_SDI (io), W8 GPIO1_A3/UART0_RTS (io), Y6 GPIO3_C5/SDMMC1_CLKO (io), Y7 GPIO3_D0/SDMMC1_PWR_EN (io), Y8 GPIO0_C5/I2S1_SDO (io), Y11 GPIO0_C0/I2S1_CLK (io)
part J pins: AA11 GPIO4_C0/SMC_D0/TRACE_D0 (io), AA13 GPIO4_C4/SMC_D4/TRACE_D4 (io), AA14 GPIO4_D0/SMC_D8/TRACE_D8 (io), AA18 GPIO4_D3/SMC_D11/TRACE_D11 (io), AA19 GPIO4_D1/SMC_D9/TRACE_D9 (io), AA20 GPIO4_D5/SMC_D13/TRACE_D13 (io), AA21 GPIO0_D5/I2S2_SDO/SMC_A1 (io), AA22 GPIO0_D4/I2S2_SDI/SMC_A0 (io), AB12 GPIO4_C6/SMC_D6/TRACE_D6 (io), AB18 GPIO4_C3/SMC_D3/TRACE_D3 (io), AB19 GPIO4_D6/SMC_D14/TRACE_D14 (io), AB20 GPIO0_C7/SMC_A3/TRACE_CTL (io), AB21 GPIO0_D2/I2S2_LRCK_RX/SMC_OEN (io), AB23 GPIO0_C6/SMC_A2/TRACE_CLK (io), AC19 GPIO4_D7/SMC_D15/TRACE_D15 (io), AC20 GPIO4_D4/SMC_D12/TRACE_D12 (io), AC22 GPIO0_D3/I2S2_LRCK_TX/SMC_ADVN (io), R17 SMC_VCC (power), W14 GPIO4_C7/SMC_D7/TRACE_D7 (io), Y10 GPIO4_C1/SMC_D1/TRACE_D1 (io), Y16 GPIO4_C2/SMC_D2/TRACE_D2 (io), Y18 GPIO4_C5/SMC_D5/TRACE_D5 (io), Y19 GPIO4_D2/SMC_D10/TRACE_D10 (io), Y20 GPIO0_D1/I2S2_SCLK/SMC_WEN (io), Y23 GPIO0_D0/I2S2_CLK/SMC_CSN0 (io)
part K pins: AB22 FLASH_D0/EMMC_D0 (io), M17 FLASH_VCC0 (power), N17 FLASH_VCC1 (power), T18 GPIO4_B0/FLASH_CS1 (io), T19 GPIO4_B1/FLASH_CS2/EMMC_CMD (io), T20 GPIO4_B2/FLASH_CS3/EMMC_RST (io), T22 FLASH_ALE (out), T23 FLASH_CS0 (out), U21 FLASH_WP/EMMC_PWR_EN (out), U22 FLASH_D7/EMMC_D7 (io), U23 FLASH_D6/EMMC_D6 (io), V19 FLASH_RDN (out), V20 FLASH_CLE (out), V21 FLASH_RDY (out), V22 FLASH_D5/EMMC_D5 (io), W20 FLASH_WRN (out), W21 GPIO3_D7/FLASH_DQS/EMMC_CLKO (io), W22 FLASH_D4/EMMC_D4 (io), W23 FLASH_D3/EMMC_D3 (io), Y21 FLASH_D1/EMMC_D1 (io), Y22 FLASH_D2/EMMC_D2 (io)
part L pins: L18 GPIO0_B4/I2S0_D0 (io), L19 GPIO0_B7/I2S0_D3 (io), L21 GPIO1_B2/SPDIF_TX (io), L22 GPIO0_B5/I2S0_D1 (io), N10 GPIO0_B2/I2S0_LRCK_RX (io), N18 GPIO0_B6/I2S0_D2 (io), N21 GPIO0_B1/I2S0_SCLK (io), P19 GPIO0_A7/I2S0_SDI (io), P21 GPIO0_B3/I2S0_LRCK_TX (io), R21 GPIO0_B0/I2S0_CLK (io)
part M pins: G21 GPIO0_A3/PWM0 (io), G22 GPIO0_D6/PWM2 (io), G23 GPIO0_A4/PWM1 (io), H21 GPIO0_D7/PWM3 (io), H22 GPIO3_A1/I2C2_SCL (io), H23 GPIO2_D4/I2C0_SDA (io), J22 GPIO2_D5/I2C0_SCL (io), K20 GPIO3_D6/UART3_RTS (io), K21 GPIO3_D4/UART3_SOUT (io), K22 GPIO3_D3/UART3_SIN (io), K23 GPIO2_D6/I2C1_SDA (io), L20 GPIO3_D5/UART3_CTS (io), L23 GPIO1_B1/UART2_SOUT (io), M11 GPIO2_D7/I2C1_SCL (io), M22 GPIO1_B0/UART2_SIN (io), N19 GPIO3_A0/I2C2_SDA (io)
part N pins: A7 DDR_D27 (io), A8 DDR_DQS3n (out), A10 DDR_D14 (io), A11 DDR_DQS1n (out), A13 DDR_CS1 (out), A14 DDR_BA1 (out), A16 DDR_CLKn (out), A17 DDR_A11 (out), A19 DDR_D18 (io), A20 DDR_D19 (io), A22 DDR_DQS2n (out), A23 DDR_D23 (io), B7 DDR_D26 (io), B8 DDR_DQS3 (out), B9 DDR_D31 (io), B10 DDR_D12 (io), B11 DDR_DQS1 (out), B12 DDR_D15 (io), B13 DDR_CS0 (out), B14 DDR_BA0 (out), B15 DDR_A0 (out), B16 DDR_CLK (out), B17 DDR_A9 (out), B18 DDR_DM2 (out), B19 DDR_PZQ (in), B20 DDR_D21 (io), B21 DDR_D20 (io), B22 DDR_DQS2 (out), B23 DDR_D22 (io), C7 DDR_D25 (io), C8 DDR_D30 (io), C9 DDR_D8 (io), C10 DDR_D13 (io), C11 DDR_D11 (io), C12 DDR_D9 (io), C13 DDR_CKE1 (out), C14 DDR_RASn (out), C15 DDR_BA2 (out), C16 DDR_A7 (out), C17 DDR_A8 (out), C18 DDR_A13 (out), C19 DDR_ODT0 (out), C20 DDR_D17 (io), C21 DDR_D16 (io), C22 DDR_DM0 (out), D7 DDR_D24 (io), D8 DDR_D29 (io), D10 DDR_DM1 (out), D11 DDR_D10 (io), D13 DDR_CKE0 (out), D14 DDR_A1 (out), D16 DDR_A4 (out), D17 DDR_A5 (out), D18 DDR_A12 (out), D19 DDR_A2 (out), D20 DDR_D6 (io), D21 DDR_D3 (io), D22 DDR_D1 (io), D23 DDR_D0 (io), E7 DDR_DM3 (out), E8 DDR_D28 (io), E10 DDR_RETEN (in), E11 DDR_CASn (out), E13 DDR_WEn (out), E14 DDR_A3 (out), E16 DDR_A10 (out), E17 DDR_A14 (out), E18 DDR_ODT1 (out), E20 DDR_D7 (io), E21 DDR_D2 (io), E22 DDR_DQS0 (out), E23 DDR_DQS0n (out), F10 MVDD1 (power), F11 DDR_RESET (out), F13 DDR_VREF (power), F14 MVDD2 (power), F16 DDR_A6 (out), F17 MVDD3 (power), F21 DDR_D5 (io), F22 DDR_D4 (io), G9 MVDD4 (power), G11 MVDD5 (power), G13 MVDD6 (power), G15 MVDD7 (power), G18 MVDD7 (power)
part O pins: A1 HDMI_TX2 (out), A2 HDMI_TX1 (out), A4 HDMI_TX0 (out), A5 HDM I_TXC (out), B1 HDMI_TX2n (out), B2 HDMI_TX1n (out), B4 HDMI_TX0n (out), B5 HDM I_TXCn (out), C2 HDM I_REXT (out), F7 VDD25_HDMI (power), F8 VDD11_HDMI (power), J21 GPIO0_A1/HDMI_I2C_SCL (io), K18 GPIO0_A2/HDMI_I2C_SDA (io), K19 GPIO0_A0/HDMI_HOT_PLUG_IN (io)
part P pins: G8 CVDD1 (power), G12 CVDD2 (power), G16 CVDD3 (power), H17 CVDD4 (power), J17 VCCIO2 (power), K17 CVDD5 (power), L7 CVDD6 (power), L17 VCCIO1 (power), P7 VCCIO3 (power), P17 CVDD7 (power), R6 AVDD1 (power), R7 AVDD2 (power), T6 AVDD3 (power), T7 AVDD4 (power), T17 CVDD8 (power), U6 AVDD5 (power), U8 AVDD6 (power), U9 AVDD7 (power), U10 AVDD8 (power), U11 AVDD9 (power), V7 AVDD10 (power), V8 AVDD11 (power), V10 AVDD12 (power), W10 VCCIO4 (power), W11 AVDD_COM (out)
part Q pins: AA16 VSS86 (power), AA17 VSS87 (power), AB13 VSS88 (power), B3 VSS1 (power), B6 VSS2 (power), G10 VSS3 (power), G14 VSS4 (power), H8 VSS5 (power), H9 VSS6 (power), H10 VSS7 (power), H11 VSS8 (power), H12 VSS9 (power), H13 VSS10 (power), H14 VSS11 (power), H15 VSS12 (power), H16 VSS13 (power), J8 VSS14 (power), J9 VSS15 (power), J10 VSS16 (power), J11 VSS17 (power), J12 VSS18 (power), J13 VSS19 (power), J14 VSS20 (power), J15 VSS21 (power), J16 VSS22 (power), K8 VSS23 (power), K9 VSS24 (power), K10 VSS25 (power), K11 VSS26 (power), K12 VSS27 (power), K13 VSS28 (power), K14 VSS29 (power), K15 VSS30 (power), K16 VSS31 (power), L8 VSS32 (power), L9 VSS33 (power), L10 VSS34 (power), L11 VSS35 (power), L12 VSS36 (power), L13 VSS37 (power), L14 VSS38 (power), L15 VSS39 (power), L16 VSS40 (power), M8 VSS41 (power), M9 VSS42 (power), M10 VSS43 (power), M11 VSS44 (power), M12 VSS45 (power), M13 VSS46 (power), M14 VSS47 (power), M15 VSS48 (power), M16 VSS49 (power), N8 VSS50 (power), N9 VSS51 (power), N10 VSS52 (power), N11 VSS53 (power), N12 VSS54 (power), N13 VSS55 (power), N14 VSS56 (power), N15 VSS57 (power), N16 VSS58 (power), P8 VSS59 (power), P9 VSS60 (power), P10 VSS61 (power), P11 VSS62 (power), P12 VSS63 (power), P13 VSS64 (power), P14 VSS65 (power), P15 VSS66 (power), P16 VSS67 (power), R8 VSS68 (power), R9 VSS69 (power), R10 VSS70 (power), R11 VSS71 (power), R12 VSS72 (power), R13 VSS73 (power), R14 VSS74 (power), R15 VSS75 (power), R16 VSS76 (power), T8 VSS77 (power), T9 VSS78 (power), T10 VSS79 (power), T11 VSS80 (power), T12 VSS81 (power), T13 VSS82 (power), T14 VSS83 (power), T15 VSS84 (power), T16 VSS85 (power)

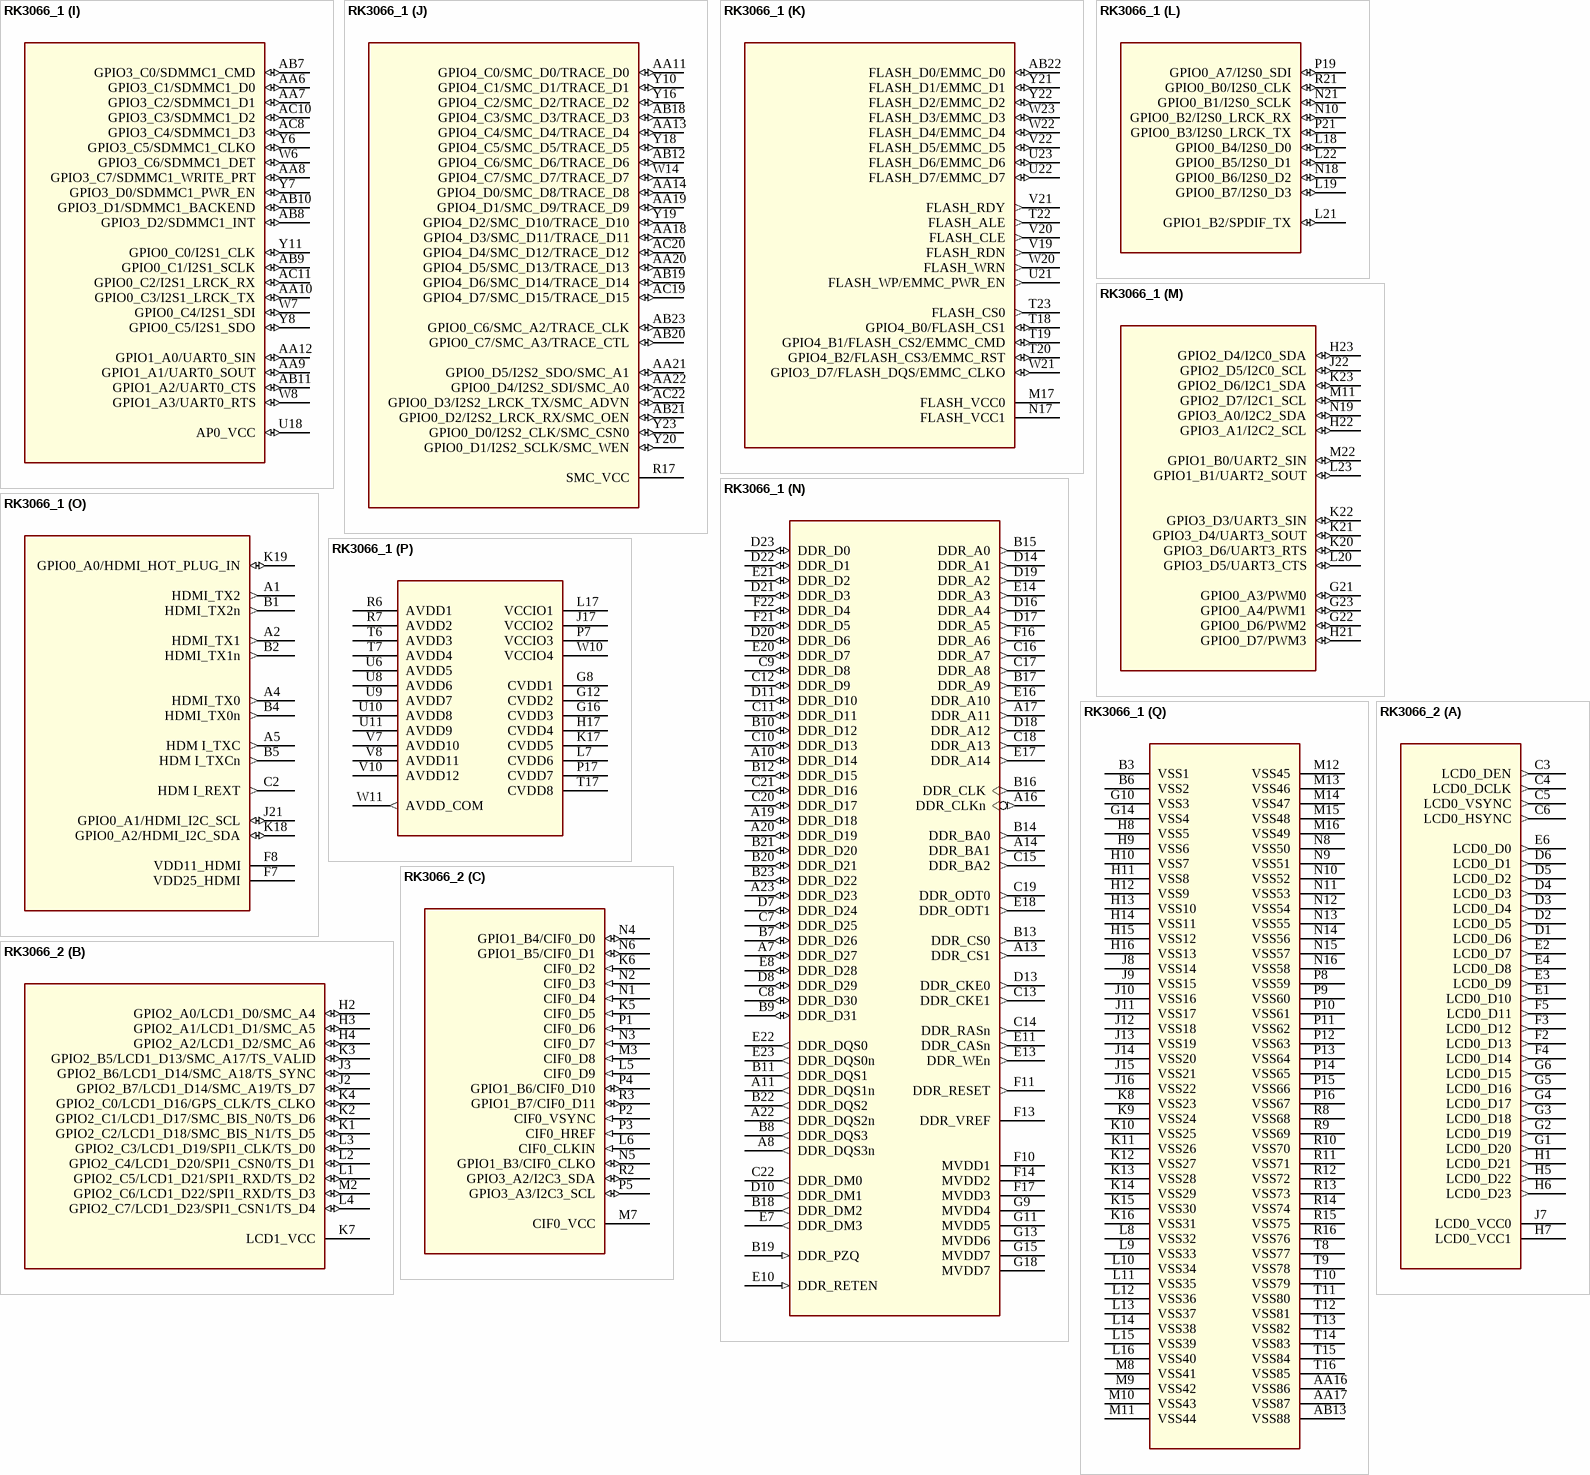
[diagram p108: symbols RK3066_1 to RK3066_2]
